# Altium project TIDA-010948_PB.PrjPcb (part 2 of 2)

## Sheet TIDA-010948_PB_Communication.SchDoc
size A2; Date: Not shown in title block; ApprovedBy: Not shown in title block; CheckedBy: Not shown in title block; Author: Not shown in title block; CompanyName: Not shown in title block; Engineer: Not shown in title block; Organization: Not shown in title block; Address1: Not shown in title block; Address2: Not shown in title block; Address3: Not shown in title block; Address4: Not shown in title block; DocumentNumber: 1; Revision: Use project parameter SCH_Rev; SheetNumber: 7; SheetTotal: 10; PageSetup: Record=PageOptions¦CenterHorizontal=True¦CenterVertical=True¦PrintScale=0.69¦XCorrection=1.00¦YCorrection=1.00¦PrintKind=0¦BorderSize=5000000¦LeftOffset=0¦BottomOffset=0¦Orientation=2¦PaperLength=1000¦PaperWidth=1000¦Scale=100¦PaperSource=15¦PrintQuality=600¦MediaType=1¦DitherType=10¦PaperKind=Letter¦PrintScaleMode=1
Used 5 times, as channels U_Communication_1, U_Communication_2, U_Communication_3, U_Communication_4, U_Communication_5. Parts and nets are listed once, with the designators drawn on the sheet.
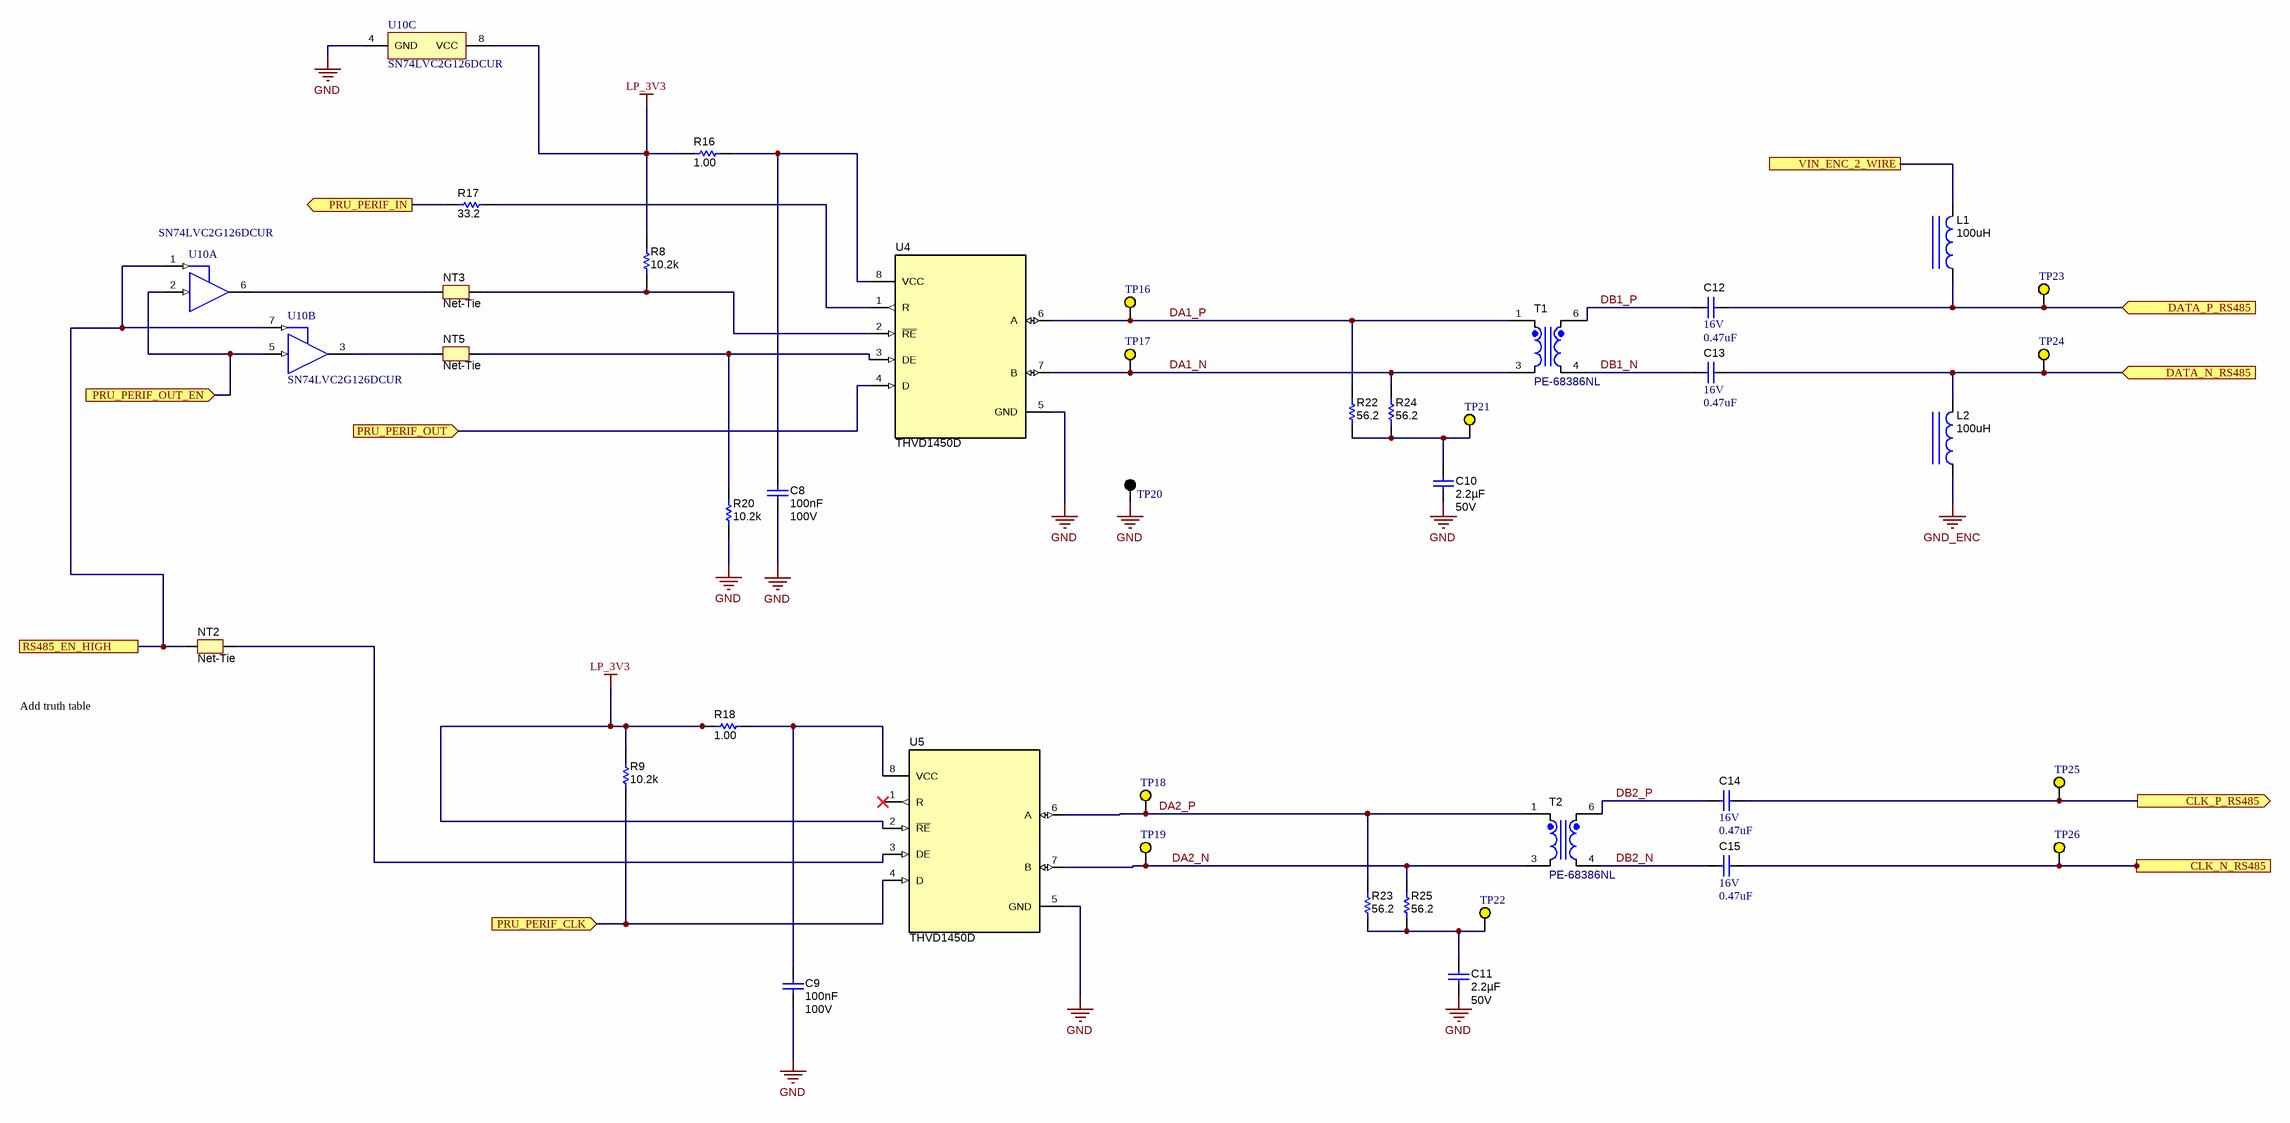
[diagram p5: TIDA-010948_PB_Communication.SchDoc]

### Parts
C8  Cap_F: 100nF  VDC_V: 100V  [0603L]  (hidden comment: GRM188R72A104KA35D)
C9  Cap_F: 100nF  VDC_V: 100V  [0603L]  (hidden comment: GRM188R72A104KA35D)
C10  Cap_F: 2.2µF  VDC_V: 50V  [0805L]  (hidden comment: CGA4J3X7R1H225K125AB)
C11  Cap_F: 2.2µF  VDC_V: 50V  [0805L]  (hidden comment: CGA4J3X7R1H225K125AB)
C12  VDC_V: 16V  ValueDisplayed: 0.47uF  [1206L]  (hidden comment: ECPU1C474MA5)
C13  VDC_V: 16V  ValueDisplayed: 0.47uF  [1206L]  (hidden comment: ECPU1C474MA5)
C14  VDC_V: 16V  ValueDisplayed: 0.47uF  [1206L]  (hidden comment: ECPU1C474MA5)
C15  VDC_V: 16V  ValueDisplayed: 0.47uF  [1206L]  (hidden comment: ECPU1C474MA5)
L1  ValueDisplayed: 100uH  [WE-TPC_4828]  (hidden comment: 744043101)
L2  ValueDisplayed: 100uH  [WE-TPC_4828]  (hidden comment: 744043101)
NT2  Net-Tie  [Net-Tie_0805_HV_NoOverlay]  (net tie, no BOM)
NT3  Net-Tie  [Net-Tie_0805_HV_NoOverlay]  (net tie, no BOM)
NT5  Net-Tie  [Net-Tie_0805_HV_NoOverlay]  (net tie, no BOM)
R8  ValueDisplayed: 10.2k  [0603L]  (hidden comment: CRCW060310K2FKEA)
R9  ValueDisplayed: 10.2k  [0603L]  (hidden comment: CRCW060310K2FKEA)
R16  ValueDisplayed: 1.00  [0603L]  (hidden comment: CRCW06031R00FKEA)
R17  ValueDisplayed: 33.2  [0603L]  (hidden comment: CRCW060333R2FKEA)
R18  ValueDisplayed: 1.00  [0603L]  (hidden comment: CRCW06031R00FKEA)
R20  ValueDisplayed: 10.2k  [0603L]  (hidden comment: CRCW060310K2FKEA)
R22  ValueDisplayed: 56.2  [0603L]  (hidden comment: CRCW060356R2FKEA)
R23  ValueDisplayed: 56.2  [0603L]  (hidden comment: CRCW060356R2FKEA)
R24  ValueDisplayed: 56.2  [0603L]  (hidden comment: CRCW060356R2FKEA)
R25  ValueDisplayed: 56.2  [0603L]  (hidden comment: CRCW060356R2FKEA)
T1  PE-68386NL  [PULSE_PE-68386NL]
T2  PE-68386NL  [PULSE_PE-68386NL]
TP16  5004  [Keystone5004]  (value not drawn)
TP17  5004  [Keystone5004]  (value not drawn)
TP18  5004  [Keystone5004]  (value not drawn)
TP19  5004  [Keystone5004]  (value not drawn)
TP20  5001  [Keystone5001]  (value not drawn)
TP21  5004  [Keystone5004]  (value not drawn)
TP22  5004  [Keystone5004]  (value not drawn)
TP23  5004  [Keystone5004]  (value not drawn)
TP24  5004  [Keystone5004]  (value not drawn)
TP25  5004  [Keystone5004]  (value not drawn)
TP26  5004  [Keystone5004]  (value not drawn)
U4  THVD1450D  [D0008A_N]
U5  THVD1450D  [D0008A_N]
U10  SN74LVC2G126DCUR  [DCU0008A_N]  (parts A,B,C of 3)

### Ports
CLK_N_RS485 (out), CLK_P_RS485 (out), DATA_N_RS485 (in), DATA_P_RS485 (in), PRU_PERIF_CLK (in), PRU_PERIF_IN (out), PRU_PERIF_OUT (in), PRU_PERIF_OUT_EN (in), RS485_EN_HIGH, VIN_ENC_2_WIRE

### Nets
GND: C8.2 C9.2 C10.2 C11.2 R20.1 TP20.1 U4.5(GND) U5.5(GND) U10.4(GND)
GND_ENC: L2.1
LP_3V3: R8.2 R9.2 R16.1 R18.1 U5.2(~{RE}) U10.8(VCC)
CLK_N_RS485: C15.1 TP26.1 ; port CLK_N_RS485
CLK_P_RS485: C14.1 TP25.1 ; port CLK_P_RS485
DA1_N: R24.2 T1.3 TP17.1 U4.7(B)
DA1_P: R22.2 T1.1 TP16.1 U4.6(A)
DA2_N: R25.2 T2.3 TP19.1 U5.7(B)
DA2_P: R23.2 T2.1 TP18.1 U5.6(A)
DATA_N_RS485: C13.1 L2.2 TP24.1 ; port DATA_N_RS485
DATA_P_RS485: C12.1 L1.1 TP23.1 ; port DATA_P_RS485
DB1_N: C13.2 T1.4
DB1_P: C12.2 T1.6
DB2_N: C15.2 T2.4
DB2_P: C14.2 T2.6
PRU_PERIF_CLK: R9.1 U5.4(D) ; port PRU_PERIF_CLK
PRU_PERIF_IN: R17.1 ; port PRU_PERIF_IN
PRU_PERIF_OUT: U4.4(D) ; port PRU_PERIF_OUT
PRU_PERIF_OUT_EN: U10.2(1A) U10.5(2A) ; port PRU_PERIF_OUT_EN
RS485_EN_HIGH: NT2.1 U10.1(1OE) U10.7(2OE) ; port RS485_EN_HIGH
VIN_ENC_2_WIRE: L1.2 ; port VIN_ENC_2_WIRE
NetC8_1: C8.1 R16.2 U4.8(VCC)
NetC9_1: C9.1 R18.2 U5.8(VCC)
NetC10_1: C10.1 R22.1 R24.1 TP21.1
NetC11_1: C11.1 R23.1 R25.1 TP22.1
NetNT2_2: NT2.2 U5.3(DE)
NetNT3_1: NT3.1 U10.6(1Y)
NetNT3_2: NT3.2 R8.1 U4.2(~{RE})
NetNT5_1: NT5.1 U10.3(2Y)
NetNT5_2: NT5.2 R20.2 U4.3(DE)
NetR17_2: R17.2 U4.1(R)

Not connected (* = marked no-connect by the designer): U5 1(R)*

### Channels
U_Communication_1: designators end in A; ports CLK_N_RS485=CLK_N CLK_P_RS485=CLK_P DATA_N_RS485=DATA_N DATA_P_RS485=DATA_P PRU_PERIF_CLK=eQEP3_A / PRU0_PERIF0_CLK PRU_PERIF_IN=PRU0_PERIF0_IN PRU_PERIF_OUT=eQEP3_B / PRU0_PERIF0_OUT PRU_PERIF_OUT_EN=eQEP4_A / PRU0_PERIF0_OUT_EN RS485_EN_HIGH=RS485_EN_HIGH VIN_ENC_2_WIRE=VOUT_ENC_2_WIRE_B
U_Communication_2: designators end in B; ports CLK_N_RS485=CLK_N CLK_P_RS485=CLK_P DATA_N_RS485=DATA_N DATA_P_RS485=DATA_P PRU_PERIF_CLK=eQEP4_B / PRU0_PERIF1_CLK PRU_PERIF_IN=PRU0_PERIF1_IN PRU_PERIF_OUT=eQEP5_A / PRU0_PERIF1_OUT PRU_PERIF_OUT_EN=eQEP5_B / PRU0_PERIF1_OUT_EN RS485_EN_HIGH=RS485_EN_HIGH VIN_ENC_2_WIRE=VOUT_ENC_2_WIRE_B
U_Communication_3: designators end in C; ports CLK_N_RS485=CLK_N CLK_P_RS485=CLK_P DATA_N_RS485=DATA_N DATA_P_RS485=DATA_P PRU_PERIF_CLK=eQEP3_I / PRU0_PERIF2_CLK PRU_PERIF_IN=PRU0_PERIF2_IN PRU_PERIF_OUT=PRU0_PERIF2_OUT PRU_PERIF_OUT_EN=eQEP5_I / PRU0_PERIF2_OUT_EN RS485_EN_HIGH=RS485_EN_HIGH VIN_ENC_2_WIRE=VOUT_ENC_2_WIRE_B
U_Communication_4: designators end in D; ports CLK_N_RS485=CLK_N CLK_P_RS485=CLK_P DATA_N_RS485=DATA_N DATA_P_RS485=DATA_P PRU_PERIF_CLK=eQEP0_A / PRU1_PERIF0_CLK PRU_PERIF_IN=eQEP0_I / PRU1_PERIF0_IN PRU_PERIF_OUT=eQEP0_B / PRU1_PERIF0_OUT PRU_PERIF_OUT_EN=PRU1_PERIF0_OUT_EN RS485_EN_HIGH=RS485_EN_HIGH VIN_ENC_2_WIRE=VOUT_ENC_2_WIRE_A
U_Communication_5: designators end in E; ports CLK_N_RS485=CLK_N CLK_P_RS485=CLK_P DATA_N_RS485=DATA_N DATA_P_RS485=DATA_P PRU_PERIF_CLK=PRU1_PERIF2_CLK PRU_PERIF_IN=PRU1_PERIF2_IN PRU_PERIF_OUT=PRU1_PERIF2_OUT PRU_PERIF_OUT_EN=PRU_PERIF_OUT_EN RS485_EN_HIGH=RS485_EN_HIGH VIN_ENC_2_WIRE=VOUT_ENC_2_WIRE_A

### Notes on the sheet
- (near NT2) Add truth table

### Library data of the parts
C8 C9 = CMP-0007469-4: CAP, CERM, 0.1 uF, 100 V, +/- 10%, X7R, 0603; Manufacturer: MuRata; TaMin_C: -55°C; Polarized: N; SizeAreaWB_mm2: 4.68; Value1: Unknown; U/M: EA; Value: 0.1uF; TaMax_C: 125°C; SizeZ_mm: 1; SizeX_mm: 1.6; SizeY_mm: 0.8; Cap_Case: 0603; SizeArea_mm2: 1.28; AEC Category: Q200
C10 C11 = CMP-0007977-2: CAP, CERM, 2.2 uF, 50 V, +/- 10%, X7R, AEC-Q200 Grade 1, 0805; Manufacturer: TDK; TaMin_C: -55°C; ESR_ohm: 3.288m; Polarized: N; SizeAreaWB_mm2: 6.75; Value1: 0.003288 ohm; U/M: EA; Value: 2.2uF; TaMax_C: 125°C; SizeZ_mm: 1.45; SizeX_mm: 2; SizeY_mm: 1.25; Cap_Case: 0805; SizeArea_mm2: 2.5; AEC Qualified: Y; IRMS_A: 3.60029A; AEC Grade: 1; AEC Category: Q200
C12-C15 = CMP-0012479-3: CAP, Film, 0.47 uF, 16 V, +/- 20%, 1206 SMD; Manufacturer: Panasonic; TaMin_C: -40°C; Polarized: N; SizeAreaWB_mm2: 10.92; Value1: Unknown; Value: 0.47uF; TaMax_C: 85°C; SizeZ_mm: 1.35; SizeX_mm: 3.2; SizeY_mm: 1.6; Cap_Case: 1206; SizeArea_mm2: 5.12; Cap_F: 470nF; AEC Category: Q200
L1 L2 = CMP-0064404-2: Inductor, Shielded Drum Core, Ferrite, 100 uH, 0.3 A, 0.52 ohm, SMD; Manufacturer: Wurth Elektronik; Isat: 0.3A @ 35% inductance drop; Irms: 0.51A @ 30C rise; Green_Lifecycle: Active; SizeAreaWB_mm2: 33.64; DCR_ohm: 0.52; Green_REACh: Passed; Value: 100uH; Imax_A: 300mA; SizeZ_mm: 3; SizeX_mm: 4.8; Value2: 0.3A; SizeArea_mm2: 23.04; Ind_H: 100µH; AEC Category: Q200
NT2 NT3 NT5 = CMP-0078142-6: Single point connection between nets.
R8 R9 R20 = CMP-0021999-4: RES, 10.2 k, 1%, 0.1 W, AEC-Q200 Grade 0, 0603; Manufacturer: Vishay-Dale; Power_W: 100mW; TempCo: 100 ppm/C; Value_Code: 10k2; Value: 10.2k; EIA_Code: E96; SizeX_mm: 1.6; SizeY_mm: 0.8; SizeZ_mm: 1; Value2: 0.1W; SizeArea_mm2: 1.28; AEC Qualified: Y; VDC_V: 75V; AEC Category: Q200; AEC Grade: 0
R16 R18 = CMP-0022170-4: RES, 1.00, 1%, 0.1 W, AEC-Q200 Grade 0, 0603; Manufacturer: Vishay-Dale; Power_W: 100mW; TempCo: 100 ppm/C; Value_Code: 1R00; Value: 1.00; EIA_Code: E96; Res_ohm: 1; SizeX_mm: 1.6; SizeY_mm: 0.8; Value2: 0.1W; SizeArea_mm2: 1.28; AEC Qualified: Y; VDC_V: 75V; AEC Category: Q200; AEC Grade: 0
R17 = CMP-0022341-4: RES, 33.2, 1%, 0.1 W, AEC-Q200 Grade 0, 0603; Manufacturer: Vishay-Dale; Power_W: 100mW; TempCo: 100 ppm/C; Value_Code: 33R2; Value: 33.2; EIA_Code: E96; SizeX_mm: 1.6; SizeY_mm: 0.8; SizeZ_mm: 1; Value2: 0.1W; SizeArea_mm2: 1.28; AEC Qualified: Y; VDC_V: 75V; AEC Category: Q200; AEC Grade: 0
R22-R25 = CMP-0022500-4: RES, 56.2, 1%, 0.1 W, AEC-Q200 Grade 0, 0603; Manufacturer: Vishay-Dale; Power_W: 100mW; TempCo: 100 ppm/C; Value_Code: 56R2; Value: 56.2; EIA_Code: E96; SizeX_mm: 1.6; SizeY_mm: 0.8; SizeZ_mm: 1; Value2: 0.1W; SizeArea_mm2: 1.28; AEC Qualified: Y; VDC_V: 75V; AEC Category: Q200; AEC Grade: 0
T1 T2 = CMP-0030422-2: Transformers, Gate Drive , 785uH, SMT; Manufacturer: Pulse Engineering; LeakageInd_H: 460nH; DCR_ohm: 0.6; Lp: 785; Ind_H: 785µH
TP16-TP19 TP21-TP26 = CMP-0055141-2: Test Point, Miniature, Yellow, TH; Manufacturer: Keystone Electronics; CNHeader: FALSE; Green_Lifecycle: Active; Green_REACh: Passed; ContactFinish: Silver; CT: TRUE
TP20 = CMP-0055138-2: Test Point, Miniature, Black, TH; Manufacturer: Keystone Electronics; CNHeader: FALSE; Green_Lifecycle: Active; Green_REACh: Passed; ContactFinish: Silver; CT: TRUE
U4 U5 = CMP-0065059-3: 3.3-V to 5-V RS-485 Transceivers With +/-18-kV IEC ESD Protection, D0008A (SOIC-8); Manufacturer: Texas Instruments; Alternate PartNumber: THVD1450DR; SizeX_mm: 4.9; SizeY_mm: 6.2; CompType: IC; SizeZ_mm: 1.75; SizeArea_mm2: 30.38; SizeAreaWB_mm2: 56.58; AEC Category: Q200; AEC Qualified: N
U10 = CMP-0051824-2: Dual Bus Buffer Gate With 3-State Outputs, DCU0008A (VSSOP-8); Manufacturer: Texas Instruments; Logic: True; Voltage(Nom)(V): 1.8,2.5,3.3,5; Input Type: CMOS/TTL; ICC @ Nom Voltage(Max)(mA): 0.01; VCC(Min)(V): 1.65; Bits(#): 2; tpd @ Nom Voltage(Max)(ns): 9.8,4.9,4,3.2; 3-State Output: Yes; Technology Family: LVC; Rating: Catalog; Output Drive (IOL/IOH)(Max)(mA): 32/-32; Schmitt Trigger: No; Output Type: CMOS; F @ Nom Voltage(Max)(Mhz): 150; VCC(Max)(V): 5.5; AEC Category: Q200; AEC Qualified: N; CompType: IC; SizeAreaWB_mm2: 12.6; SizeArea_mm2: 6.4; SizeX_mm: 3.2; SizeY_mm: 2.0; SizeZ_mm: 0.9

## Sheet TIDA-010948_PB_Connectors.SchDoc
size A2; Date: Not shown in title block; ApprovedBy: Not shown in title block; CheckedBy: Not shown in title block; Author: Not shown in title block; CompanyName: Not shown in title block; Engineer: Not shown in title block; Organization: Not shown in title block; Address1: Not shown in title block; Address2: Not shown in title block; Address3: Not shown in title block; Address4: Not shown in title block; DocumentNumber: 1; Revision: Use project parameter SCH_Rev; SheetNumber: 3; SheetTotal: 9; PageSetup: Record=PageOptions¦CenterHorizontal=True¦CenterVertical=True¦PrintScale=0.69¦XCorrection=1.00¦YCorrection=1.00¦PrintKind=0¦BorderSize=5000000¦LeftOffset=0¦BottomOffset=0¦Orientation=2¦PaperLength=1000¦PaperWidth=1000¦Scale=100¦PaperSource=15¦PrintQuality=600¦MediaType=1¦DitherType=10¦PaperKind=Letter¦PrintScaleMode=1
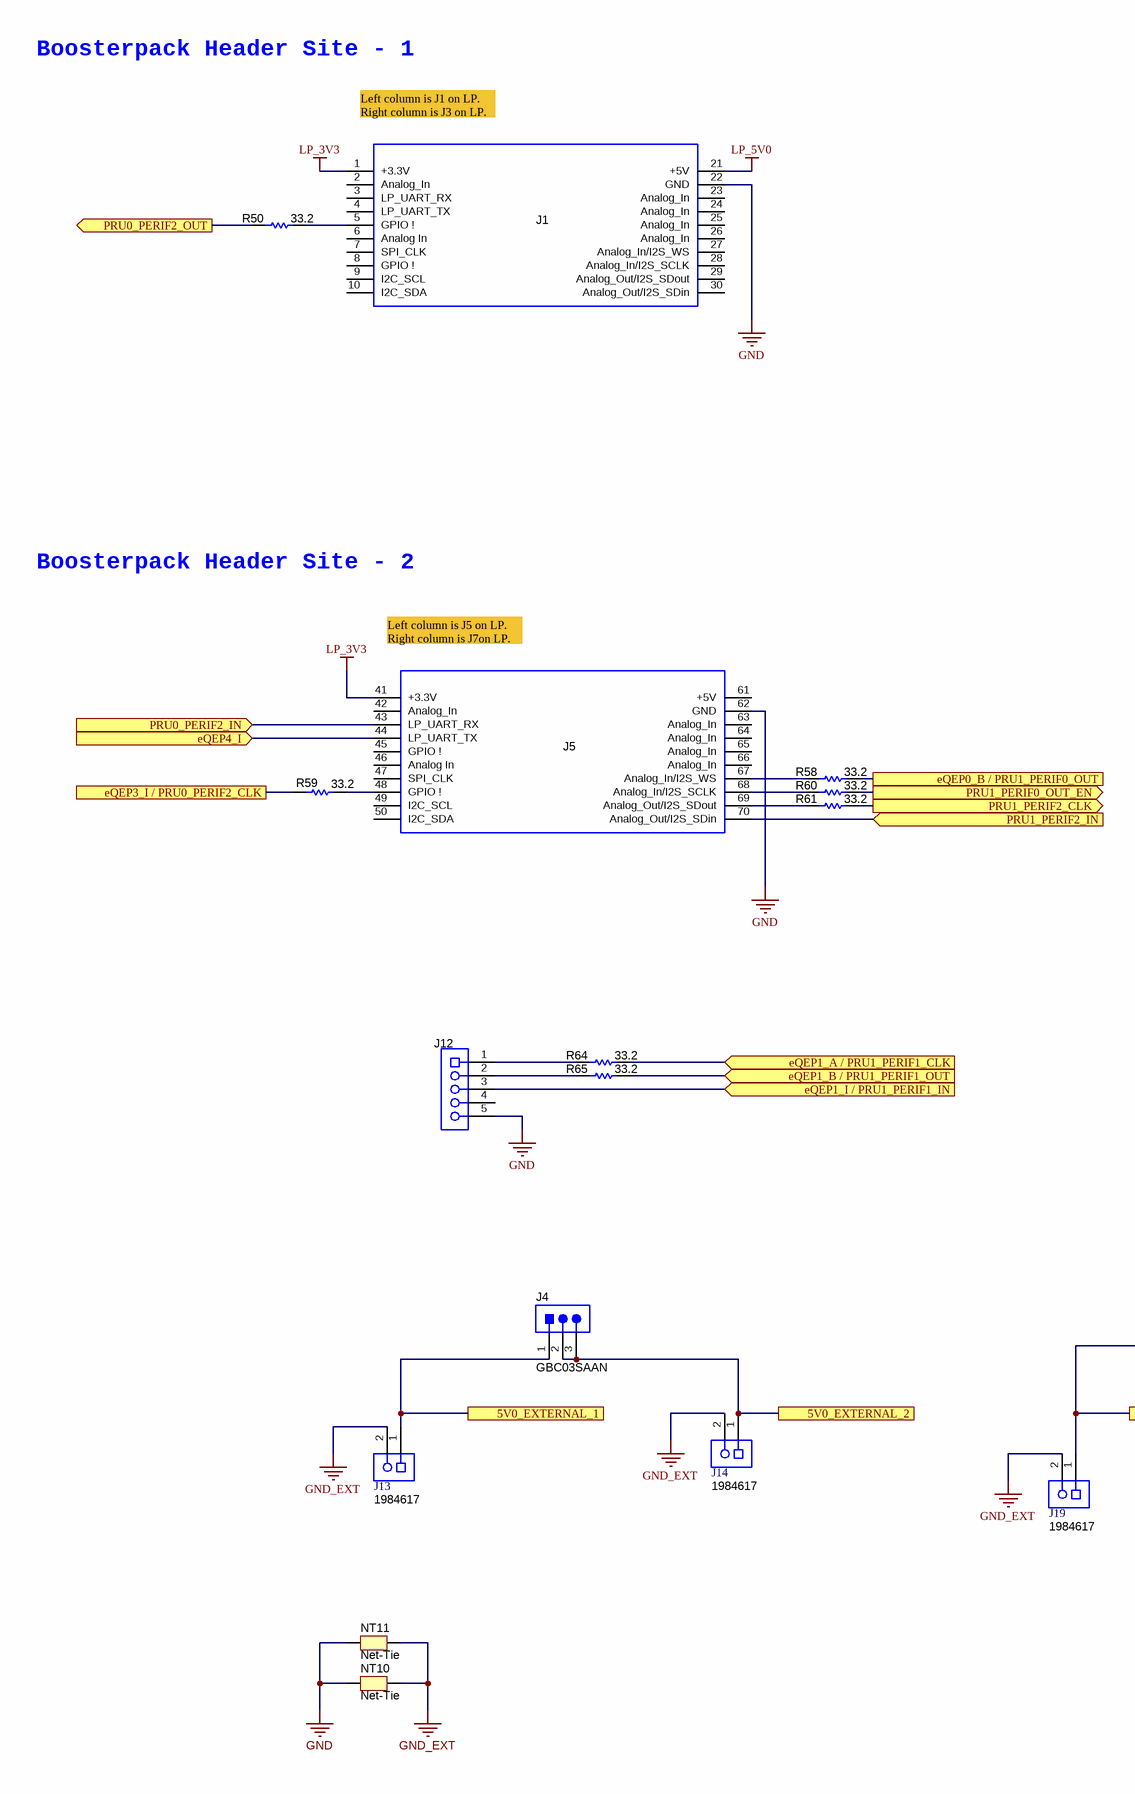
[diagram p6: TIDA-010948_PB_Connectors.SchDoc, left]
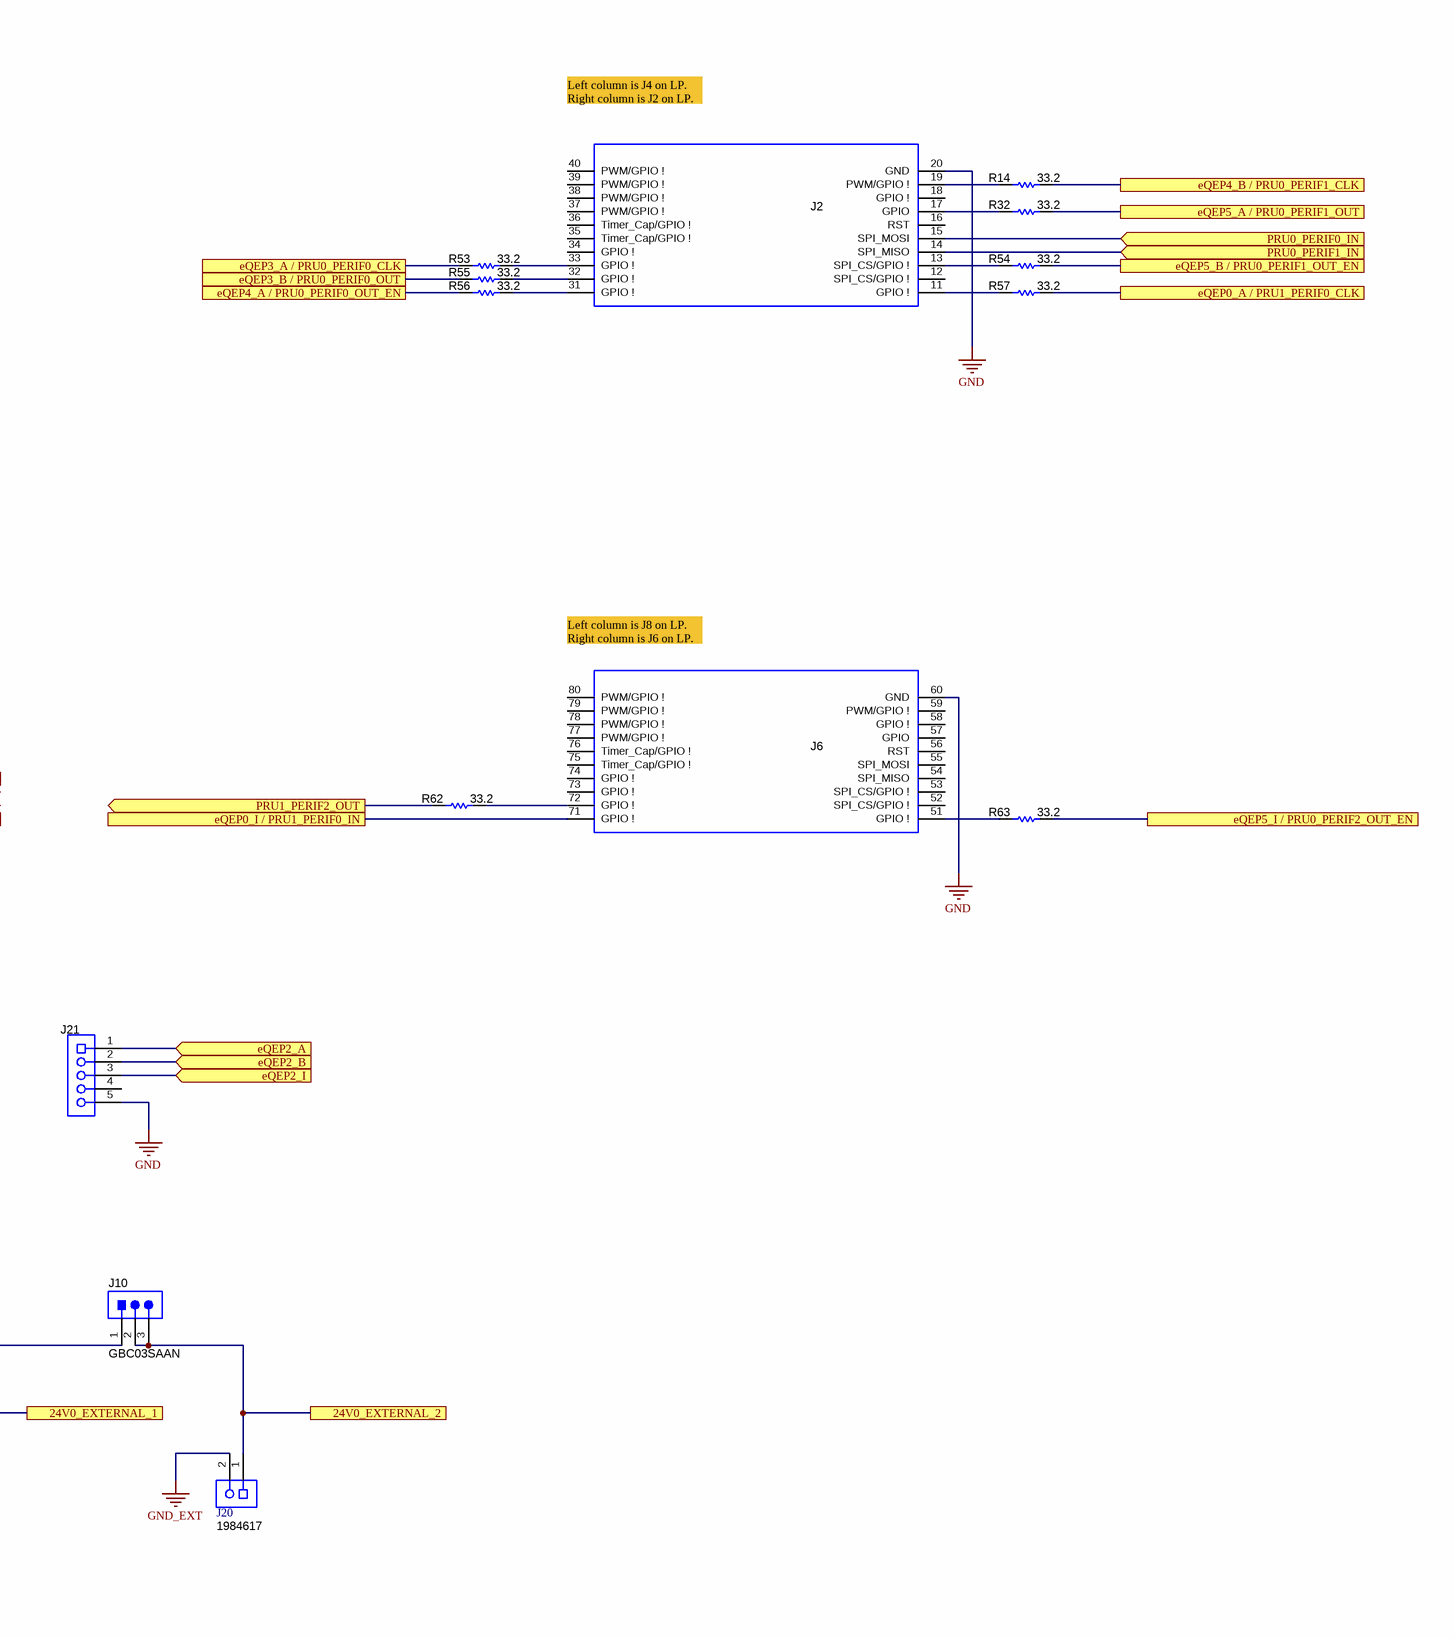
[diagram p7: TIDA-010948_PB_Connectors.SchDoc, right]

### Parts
J1  BoosterPack_40pin_J1J3  [BoosterPack_40pin_J1J3]  (value not drawn)
J2  BoosterPack_40pin_J2J4  [BoosterPack_40pin_J2J4]  (value not drawn)
J4  GBC03SAAN  [Sullins_Gxx03SAAN]
J5  BoosterPack_40pin_J5J7  [BoosterPack_40pin_J5J7]  (value not drawn)
J6  BoosterPack_40pin_J6J8  [BoosterPack_40pin_J6J8]  (value not drawn)
J10  GBC03SAAN  [Sullins_Gxx03SAAN]
J12  Receptacle_5x1  [Samtec_SSQ-105-01-x-S]  (value not drawn)
J13  1984617  [Phoenix_1984617]
J14  1984617  [Phoenix_1984617]
J19  1984617  [Phoenix_1984617]
J20  1984617  [Phoenix_1984617]
J21  Receptacle_5x1  [Samtec_SSQ-105-01-x-S]  (value not drawn)
NT10  Net-Tie  [Net-Tie_0805_HV_NoOverlay]  (net tie, no BOM)
NT11  Net-Tie  [Net-Tie_0805_HV_NoOverlay]  (net tie, no BOM)
R14  ValueDisplayed: 33.2  [0603L]  (hidden comment: CRCW060333R2FKEA)
R32  ValueDisplayed: 33.2  [0603L]  (hidden comment: CRCW060333R2FKEA)
R50  ValueDisplayed: 33.2  [0603L]  (hidden comment: CRCW060333R2FKEA)
R53  ValueDisplayed: 33.2  [0603L]  (hidden comment: CRCW060333R2FKEA)
R54  ValueDisplayed: 33.2  [0603L]  (hidden comment: CRCW060333R2FKEA)
R55  ValueDisplayed: 33.2  [0603L]  (hidden comment: CRCW060333R2FKEA)
R56  ValueDisplayed: 33.2  [0603L]  (hidden comment: CRCW060333R2FKEA)
R57  ValueDisplayed: 33.2  [0603L]  (hidden comment: CRCW060333R2FKEA)
R58  ValueDisplayed: 33.2  [0603L]  (hidden comment: CRCW060333R2FKEA)
R59  ValueDisplayed: 33.2  [0603L]  (hidden comment: CRCW060333R2FKEA)
R60  ValueDisplayed: 33.2  [0603L]  (hidden comment: CRCW060333R2FKEA)
R61  ValueDisplayed: 33.2  [0603L]  (hidden comment: CRCW060333R2FKEA)
R62  ValueDisplayed: 33.2  [0603L]  (hidden comment: CRCW060333R2FKEA)
R63  ValueDisplayed: 33.2  [0603L]  (hidden comment: CRCW060333R2FKEA)
R64  ValueDisplayed: 33.2  [0603L]  (hidden comment: CRCW060333R2FKEA)
R65  ValueDisplayed: 33.2  [0603L]  (hidden comment: CRCW060333R2FKEA)

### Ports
5V0_EXTERNAL_1, 5V0_EXTERNAL_2, 24V0_EXTERNAL_1, 24V0_EXTERNAL_2, eQEP0_A / PRU1_PERIF0_CLK, eQEP0_B / PRU1_PERIF0_OUT, eQEP0_I / PRU1_PERIF0_IN, eQEP1_A / PRU1_PERIF1_CLK (in), eQEP1_B / PRU1_PERIF1_OUT (in), eQEP1_I / PRU1_PERIF1_IN (in), eQEP2_A (in), eQEP2_B (in), eQEP2_I (in), eQEP3_A / PRU0_PERIF0_CLK, eQEP3_B / PRU0_PERIF0_OUT, eQEP3_I / PRU0_PERIF2_CLK, eQEP4_A / PRU0_PERIF0_OUT_EN, eQEP4_B / PRU0_PERIF1_CLK, eQEP4_I (in), eQEP5_A / PRU0_PERIF1_OUT, eQEP5_B / PRU0_PERIF1_OUT_EN, eQEP5_I / PRU0_PERIF2_OUT_EN, PRU0_PERIF0_IN (in), PRU0_PERIF1_IN (in), PRU0_PERIF2_IN (in), PRU0_PERIF2_OUT (out), PRU1_PERIF0_OUT_EN (out), PRU1_PERIF2_CLK (out), PRU1_PERIF2_IN (in), PRU1_PERIF2_OUT (out)

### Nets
GND: J1.22(GND) J2.20(GND) J5.62(GND) J6.60(GND) J12.5 J21.5 NT10.1 NT11.1
GND_EXT: J13.2 J14.2 J19.2 J20.2 NT10.2 NT11.2
LP_3V3: J1.1(+3.3V) J5.41(+3.3V)
LP_5V0: J1.21(+5V)
5V0_EXTERNAL_1: J4.1 J13.1 ; port 5V0_EXTERNAL_1
5V0_EXTERNAL_2: J4.2 J4.3 J14.1 ; port 5V0_EXTERNAL_2
24V0_EXTERNAL_1: J10.1 J19.1 ; port 24V0_EXTERNAL_1
24V0_EXTERNAL_2: J10.2 J10.3 J20.1 ; port 24V0_EXTERNAL_2
eQEP0_A / PRU1_PERIF0_CLK: R57.2 ; port eQEP0_A / PRU1_PERIF0_CLK
eQEP0_B / PRU1_PERIF0_OUT: R58.2 ; port eQEP0_B / PRU1_PERIF0_OUT
eQEP0_I / PRU1_PERIF0_IN: J6.71(GPIO_!) ; port eQEP0_I / PRU1_PERIF0_IN
eQEP1_A / PRU1_PERIF1_CLK: R64.2 ; port eQEP1_A / PRU1_PERIF1_CLK
eQEP1_B / PRU1_PERIF1_OUT: R65.2 ; port eQEP1_B / PRU1_PERIF1_OUT
eQEP1_I / PRU1_PERIF1_IN: J12.3 ; port eQEP1_I / PRU1_PERIF1_IN
eQEP2_A: J21.1 ; port eQEP2_A
eQEP2_B: J21.2 ; port eQEP2_B
eQEP2_I: J21.3 ; port eQEP2_I
eQEP3_A / PRU0_PERIF0_CLK: R53.1 ; port eQEP3_A / PRU0_PERIF0_CLK
eQEP3_B / PRU0_PERIF0_OUT: R55.1 ; port eQEP3_B / PRU0_PERIF0_OUT
eQEP3_I / PRU0_PERIF2_CLK: R59.1 ; port eQEP3_I / PRU0_PERIF2_CLK
eQEP4_A / PRU0_PERIF0_OUT_EN: R56.1 ; port eQEP4_A / PRU0_PERIF0_OUT_EN
eQEP4_B / PRU0_PERIF1_CLK: R14.2 ; port eQEP4_B / PRU0_PERIF1_CLK
eQEP4_I: J5.44(LP_UART_TX) ; port eQEP4_I
eQEP5_A / PRU0_PERIF1_OUT: R32.2 ; port eQEP5_A / PRU0_PERIF1_OUT
eQEP5_B / PRU0_PERIF1_OUT_EN: R54.2 ; port eQEP5_B / PRU0_PERIF1_OUT_EN
eQEP5_I / PRU0_PERIF2_OUT_EN: R63.2 ; port eQEP5_I / PRU0_PERIF2_OUT_EN
PRU0_PERIF0_IN: J2.15(SPI_MOSI) ; port PRU0_PERIF0_IN
PRU0_PERIF1_IN: J2.14(SPI_MISO) ; port PRU0_PERIF1_IN
PRU0_PERIF2_IN: J5.43(LP_UART_RX) ; port PRU0_PERIF2_IN
PRU0_PERIF2_OUT: R50.1 ; port PRU0_PERIF2_OUT
PRU1_PERIF0_OUT_EN: R60.2 ; port PRU1_PERIF0_OUT_EN
PRU1_PERIF2_CLK: R61.2 ; port PRU1_PERIF2_CLK
PRU1_PERIF2_IN: J5.70(Analog_Out/I2S_SDin) ; port PRU1_PERIF2_IN
PRU1_PERIF2_OUT: R62.1 ; port PRU1_PERIF2_OUT
NetJ1_5: J1.5(GPIO_!) R50.2
NetJ2_11: J2.11(GPIO_!) R57.1
NetJ2_13: J2.13(SPI_CS/GPIO_!) R54.1
NetJ2_17: J2.17(GPIO) R32.1
NetJ2_19: J2.19(PWM/GPIO_!) R14.1
NetJ2_31: J2.31(GPIO_!) R56.2
NetJ2_32: J2.32(GPIO_!) R55.2
NetJ2_33: J2.33(GPIO_!) R53.2
NetJ5_48: J5.48(GPIO_!) R59.2
NetJ5_67: J5.67(Analog_In/I2S_WS) R58.1
NetJ5_68: J5.68(Analog_In/I2S_SCLK) R60.1
NetJ5_69: J5.69(Analog_Out/I2S_SDout) R61.1
NetJ6_51: J6.51(GPIO_!) R63.1
NetJ6_72: J6.72(GPIO_!) R62.2
NetJ12_1: J12.1 R64.1
NetJ12_2: J12.2 R65.1

Not connected (* = marked no-connect by the designer): J1 2(Analog_In) 3(LP_UART_RX) 4(LP_UART_TX) 6(Analog_In) 7(SPI_CLK) 8(GPIO_!) 9(I2C_SCL) 10(I2C_SDA) 23(Analog_In) 24(Analog_In) 25(Analog_In) 26(Analog_In) 27(Analog_In/I2S_WS) 28(Analog_In/I2S_SCLK) 29(Analog_Out/I2S_SDout) 30(Analog_Out/I2S_SDin); J2 12(SPI_CS/GPIO_!) 16(RST) 18(GPIO_!) 34(GPIO_!) 35(Timer_Cap/GPIO_!) 36(Timer_Cap/GPIO_!) 37(PWM/GPIO_!) 38(PWM/GPIO_!) 39(PWM/GPIO_!) 40(PWM/GPIO_!); J5 42(Analog_In) 45(GPIO_!) 46(Analog_In) 47(SPI_CLK) 49(I2C_SCL) 50(I2C_SDA) 61(+5V) 63(Analog_In) 64(Analog_In) 65(Analog_In) 66(Analog_In); J6 52(SPI_CS/GPIO_!) 53(SPI_CS/GPIO_!) 54(SPI_MISO) 55(SPI_MOSI) 56(RST) 57(GPIO) 58(GPIO_!) 59(PWM/GPIO_!) 73(GPIO_!) 74(GPIO_!) 75(Timer_Cap/GPIO_!) 76(Timer_Cap/GPIO_!) 77(PWM/GPIO_!) 78(PWM/GPIO_!) 79(PWM/GPIO_!) 80(PWM/GPIO_!); J12 4; J21 4

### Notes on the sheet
- Boosterpack Header Site - 1
- Left column is J4 on LP.
  Right column is J2 on LP.
- Left column is J1 on LP.
  Right column is J3 on LP.
- Boosterpack Header Site - 2
- Left column is J5 on LP.
  Right column is J7on LP.
- Left column is J8 on LP.
  Right column is J6 on LP.

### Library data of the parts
J1 = CMP-0003837-4: Receptacle, 2.54mm, 10x2, Tin, TH; Alternate Manufacturer: Major League Electronics; Alternate PartNumber: CRD-081413-A-G; Manufacturer: Samtec; PartNumber: SSQ-110-03-T-D; Green_Lifecycle: Active; Green_REACh: Incomplete; Note: Booster Pack 40 pin J1 and J3
J2 = CMP-0078266-4: Receptacle, 2.54mm, 10x2, Tin, TH; Alternate Manufacturer: Major League Electronics; Alternate PartNumber: CRD-081413-A-G; Manufacturer: Samtec; PartNumber: SSQ-110-03-T-D; Green_Lifecycle: Active; Green_REACh: Incomplete; Note: Booster Pack 40 pin J2 and J4
J4 J10 = CMP-0054577-1: Header, 2.54 mm, 3x1, Gold, TH; Manufacturer: Sullins Connector Solutions; CT: FALSE; CNHeader: TRUE
J5 = CMP-0081070-3: Receptacle, 2.54mm, 10x2, Tin, TH; Alternate Manufacturer: Major League Electronics; Alternate PartNumber: CRD-081413-A-G; Manufacturer: Samtec; PartNumber: SSQ-110-03-T-D; Green_Lifecycle: Active; Green_REACh: Incomplete; Note: Booster Pack 40 pin J5 and J7
J6 = CMP-0081071-3: Receptacle, 2.54mm, 10x2, Tin, TH; Alternate Manufacturer: Major League Electronics; Alternate PartNumber: CRD-081413-A-G; Manufacturer: Samtec; PartNumber: SSQ-110-03-T-D; Green_Lifecycle: Active; Green_REACh: Incomplete; Note: Booster Pack 40 pin J6 and J8
J12 J21 = CMP-0077539-1: Receptacle, 2.54mm, 5x1, Gold, TH; Manufacturer: Samtec; PartNumber: SSQ-105-01-G-S; Cert_CSA: Y; CompType: Socket Strip; Current_A: 6.3A; Gender: Female; Pitch_mm: 2.54; Row_Count: 1; Voltage_V: 550V
J13 J14 J19 J20 = CMP-0055519-1: Terminal Block, 3.5mm, 2x1, TH; Manufacturer: Phoenix Contact; CNHeader: FALSE; Current_A: 17.5A; Gender: Female; Cert_CULUS: Y; Voltage_V: 200V; Row_Count: 1; Pitch_mm: 3.5; CT: TRUE
NT10 NT11 = CMP-0078142-6: Single point connection between nets.
R14 R32 R50 R53-R65 = CMP-0022341-4: as R17 on sheet TIDA-010948_PB_Communication

## Sheet TIDA-010948_PB_Encoder_connector.SchDoc
size A3; Date: Not shown in title block; ApprovedBy: Not shown in title block; CheckedBy: Not shown in title block; Author: Not shown in title block; CompanyName: Not shown in title block; Engineer: Not shown in title block; Organization: Not shown in title block; Address1: Not shown in title block; Address2: Not shown in title block; Address3: Not shown in title block; Address4: Not shown in title block; DocumentNumber: 1; Revision: Use project parameter SCH_Rev; SheetNumber: 9; SheetTotal: 10; PageSetup: Record=PageOptions¦CenterHorizontal=True¦CenterVertical=True¦PrintScale=0.69¦XCorrection=1.00¦YCorrection=1.00¦PrintKind=0¦BorderSize=5000000¦LeftOffset=0¦BottomOffset=0¦Orientation=2¦PaperLength=1000¦PaperWidth=1000¦Scale=100¦PaperSource=15¦PrintQuality=600¦MediaType=1¦DitherType=10¦PaperKind=Letter¦PrintScaleMode=1
Used 6 times, as channels U_Encoder_connector_1, U_Encoder_connector_2, U_Encoder_connector_3, U_Encoder_connector_4, U_Encoder_connector_5, U_Encoder_connector_6. Parts and nets are listed once, with the designators drawn on the sheet.
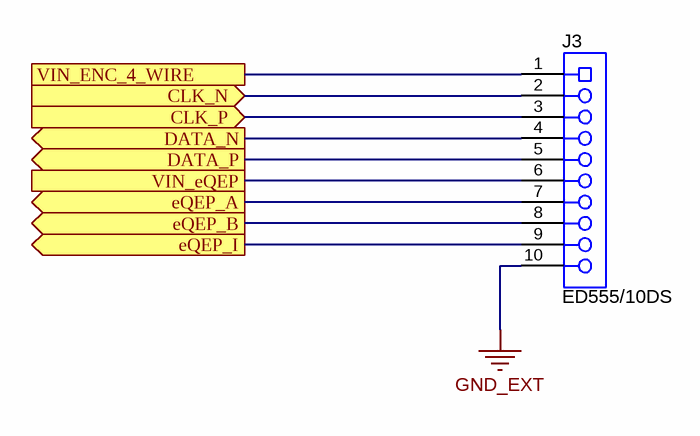
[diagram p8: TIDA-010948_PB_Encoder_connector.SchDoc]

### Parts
J3  ED555/10DS  [On-Shore_ED555_10DS]

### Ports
CLK_N (in), CLK_P (in), DATA_N (out), DATA_P (out), eQEP_A (out), eQEP_B (out), eQEP_I (out), VIN_ENC_4_WIRE, VIN_eQEP

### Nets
GND_EXT: J3.10
CLK_N: J3.2 ; port CLK_N
CLK_P: J3.3 ; port CLK_P
DATA_N: J3.4 ; port DATA_N
DATA_P: J3.5 ; port DATA_P
eQEP_A: J3.7 ; port eQEP_A
eQEP_B: J3.8 ; port eQEP_B
eQEP_I: J3.9 ; port eQEP_I
VIN_ENC_4_WIRE: J3.1 ; port VIN_ENC_4_WIRE
VIN_eQEP: J3.6 ; port VIN_eQEP

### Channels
U_Encoder_connector_1: designators end in A; ports CLK_N=CLK_N CLK_P=CLK_P DATA_N=DATA_N DATA_P=DATA_P eQEP_A=eQEP_A eQEP_B=eQEP_B eQEP_I=eQEP_I VIN_ENC_4_WIRE=VOUT__ENC_4_WIRE_A VIN_eQEP=VOUT_5V0_ENC_A
U_Encoder_connector_2: designators end in B; ports CLK_N=CLK_N CLK_P=CLK_P DATA_N=DATA_N DATA_P=DATA_P eQEP_A=eQEP1_A / PRU1_PERIF1_CLK eQEP_B=eQEP1_B / PRU1_PERIF1_OUT eQEP_I=eQEP1_I / PRU1_PERIF1_IN VIN_ENC_4_WIRE=VOUT__ENC_4_WIRE_A VIN_eQEP=VOUT_5V0_ENC_A
U_Encoder_connector_3: designators end in C; ports CLK_N=CLK_N CLK_P=CLK_P DATA_N=DATA_N DATA_P=DATA_P eQEP_A=eQEP2_A eQEP_B=eQEP2_B eQEP_I=eQEP2_I VIN_ENC_4_WIRE=VOUT__ENC_4_WIRE_A VIN_eQEP=VOUT_5V0_ENC_A
U_Encoder_connector_4: designators end in D; ports CLK_N=CLK_N CLK_P=CLK_P DATA_N=DATA_N DATA_P=DATA_P eQEP_A=eQEP_A eQEP_B=eQEP_B eQEP_I=eQEP_I VIN_ENC_4_WIRE=VOUT__ENC_4_WIRE_B VIN_eQEP=VOUT_5V0_ENC_B
U_Encoder_connector_5: designators end in E; ports CLK_N=CLK_N CLK_P=CLK_P DATA_N=DATA_N DATA_P=DATA_P eQEP_A=eQEP_A eQEP_B=eQEP_B eQEP_I=eQEP_I VIN_ENC_4_WIRE=VOUT__ENC_4_WIRE_B VIN_eQEP=VOUT_5V0_ENC_B
U_Encoder_connector_6: designators end in F; ports CLK_N=CLK_N CLK_P=CLK_P DATA_N=DATA_N DATA_P=DATA_P eQEP_A=eQEP_A eQEP_B=eQEP_B eQEP_I=eQEP_I VIN_ENC_4_WIRE=VOUT__ENC_4_WIRE_B VIN_eQEP=VOUT_5V0_ENC_B

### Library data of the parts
J3 = CMP-0084189-1: Terminal Block, 3.5mm, 10x1, TH; Manufacturer: On-Shore Technology; Pitch_mm: 3.5; Cert_VDE: Y; Gender: Female; Voltage_V: 150V; Current_A: 6A; Row_Count: 1

## Sheet TIDA-010948_PB_Level_shifter.SchDoc
size A2; Date: Not shown in title block; ApprovedBy: Not shown in title block; CheckedBy: Not shown in title block; Author: Not shown in title block; CompanyName: Not shown in title block; Engineer: Not shown in title block; Organization: Not shown in title block; Address1: Not shown in title block; Address2: Not shown in title block; Address3: Not shown in title block; Address4: Not shown in title block; DocumentNumber: 1; Revision: Use project parameter SCH_Rev; SheetNumber: 7; SheetTotal: 9; PageSetup: Record=PageOptions¦CenterHorizontal=True¦CenterVertical=True¦PrintScale=0.69¦XCorrection=1.00¦YCorrection=1.00¦PrintKind=0¦BorderSize=5000000¦LeftOffset=0¦BottomOffset=0¦Orientation=2¦PaperLength=1000¦PaperWidth=1000¦Scale=100¦PaperSource=15¦PrintQuality=600¦MediaType=1¦DitherType=10¦PaperKind=Letter¦PrintScaleMode=1
Used 2 times, as channels U_Level_shifter_1, U_Level_shifter_2. Parts and nets are listed once, with the designators drawn on the sheet.
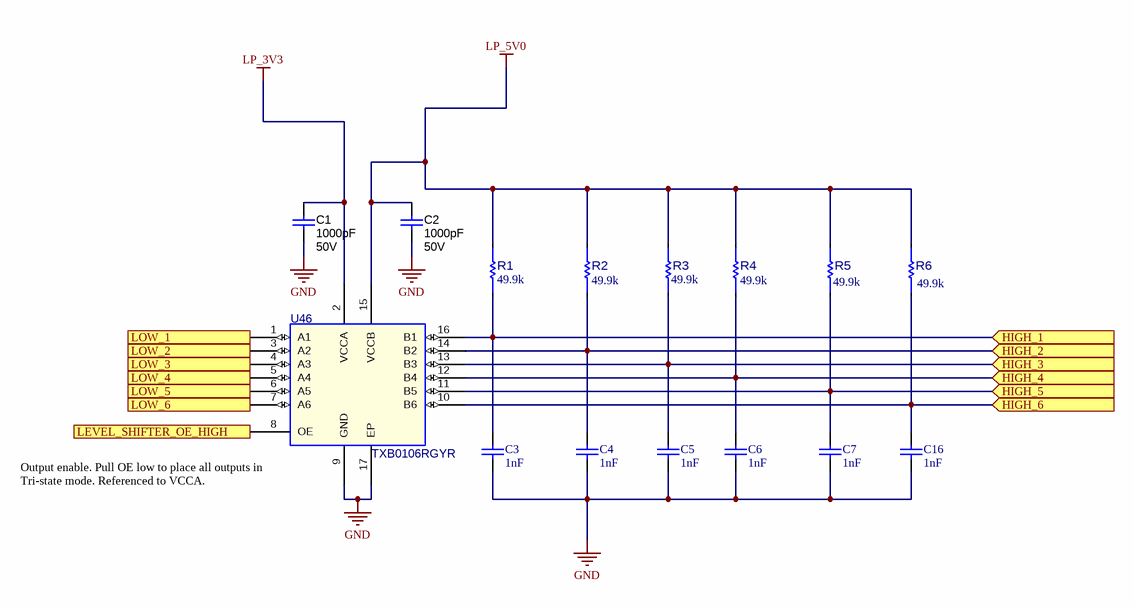
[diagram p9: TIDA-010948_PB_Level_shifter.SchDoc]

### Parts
C1  Cap_F: 1000pF  VDC_V: 50V  [0603L]  (hidden comment: GRM188R72A104KA35D)
C2  Cap_F: 1000pF  VDC_V: 50V  [0603L]  (hidden comment: GRM188R72A104KA35D)
C3  Cap_F: 1nF  [WCAP-CSGP_0603_L1.6W0.8H0.8_Reflow]  (hidden comment: 885012006085)
C4  Cap_F: 1nF  [WCAP-CSGP_0603_L1.6W0.8H0.8_Reflow]  (hidden comment: 885012006085)
C5  Cap_F: 1nF  [WCAP-CSGP_0603_L1.6W0.8H0.8_Reflow]  (hidden comment: 885012006085)
C6  Cap_F: 1nF  [WCAP-CSGP_0603_L1.6W0.8H0.8_Reflow]  (hidden comment: 885012006085)
C7  Cap_F: 1nF  [WCAP-CSGP_0603_L1.6W0.8H0.8_Reflow]  (hidden comment: 885012006085)
C16  Cap_F: 1nF  [WCAP-CSGP_0603_L1.6W0.8H0.8_Reflow]  (hidden comment: 885012006085)
R1  value 49.9k  [FP-RN73C1J49K9BTG_0603-MFG]  (hidden comment: RN73C1J49K9BTG)
R2  value 49.9k  [FP-RN73C1J49K9BTG_0603-MFG]  (hidden comment: RN73C1J49K9BTG)
R3  value 49.9k  [FP-RN73C1J49K9BTG_0603-MFG]  (hidden comment: RN73C1J49K9BTG)
R4  value 49.9k  [FP-RN73C1J49K9BTG_0603-MFG]  (hidden comment: RN73C1J49K9BTG)
R5  value 49.9k  [FP-RN73C1J49K9BTG_0603-MFG]  (hidden comment: RN73C1J49K9BTG)
R6  value 49.9k  [FP-RN73C1J49K9BTG_0603-MFG]  (hidden comment: RN73C1J49K9BTG)
U46  value TXB0106RGYR  [QFN16_19-68_160X140_1]  (hidden comment: TXB0106RGYR_VQFN16)

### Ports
HIGH_1 (in), HIGH_2 (in), HIGH_3 (in), HIGH_4 (in), HIGH_5 (in), HIGH_6 (in), LEVEL_SHIFTER_OE_HIGH, LOW_1 (out), LOW_2 (out), LOW_3 (out), LOW_4 (out), LOW_5 (out), LOW_6 (out)

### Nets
GND: C1.2 C2.2 C3.2 C4.2 C5.2 C6.2 C7.2 C16.2 U46.9(GND) U46.17(EP)
LP_3V3: C1.1 U46.2(VCCA)
LP_5V0: C2.1 R1.2 R2.2 R3.2 R4.2 R5.2 R6.2 U46.15(VCCB)
HIGH_1: C3.1 R1.1 U46.16(B1) ; port HIGH_1
HIGH_2: C4.1 R2.1 U46.14(B2) ; port HIGH_2
HIGH_3: C5.1 R3.1 U46.13(B3) ; port HIGH_3
HIGH_4: C6.1 R4.1 U46.12(B4) ; port HIGH_4
HIGH_5: C7.1 R5.1 U46.11(B5) ; port HIGH_5
HIGH_6: C16.1 R6.1 U46.10(B6) ; port HIGH_6
LEVEL_SHIFTER_OE_HIGH: U46.8(OE) ; port LEVEL_SHIFTER_OE_HIGH
LOW_1: U46.1(A1) ; port LOW_1
LOW_2: U46.3(A2) ; port LOW_2
LOW_3: U46.4(A3) ; port LOW_3
LOW_4: U46.5(A4) ; port LOW_4
LOW_5: U46.6(A5) ; port LOW_5
LOW_6: U46.7(A6) ; port LOW_6

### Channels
U_Level_shifter_1: designators end in A; ports HIGH_1=eQEP_A HIGH_2=eQEP_B HIGH_3=eQEP_I HIGH_4=eQEP_A HIGH_5=eQEP_B HIGH_6=eQEP_I LEVEL_SHIFTER_OE_HIGH=LS_OE_HIGH LOW_1=eQEP3_A / PRU0_PERIF0_CLK LOW_2=eQEP3_B / PRU0_PERIF0_OUT LOW_3=eQEP3_I / PRU0_PERIF2_CLK LOW_4=eQEP4_A / PRU0_PERIF0_OUT_EN LOW_5=eQEP4_B / PRU0_PERIF1_CLK LOW_6=eQEP4_I
U_Level_shifter_2: designators end in B; ports HIGH_1=eQEP_A HIGH_2=eQEP_B HIGH_3=eQEP_I HIGH_4=eQEP_A HIGH_5=eQEP_B HIGH_6=eQEP_I LEVEL_SHIFTER_OE_HIGH=LS_OE_HIGH LOW_1=eQEP0_A / PRU1_PERIF0_CLK LOW_2=eQEP0_B / PRU1_PERIF0_OUT LOW_3=eQEP0_I / PRU1_PERIF0_IN LOW_4=eQEP5_A / PRU0_PERIF1_OUT LOW_5=eQEP5_B / PRU0_PERIF1_OUT_EN LOW_6=eQEP5_I / PRU0_PERIF2_OUT_EN

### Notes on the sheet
- (near U46) Output enable. Pull OE low to place all outputs in Tri-state mode. Referenced to VCCA.

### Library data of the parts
C1 C2 = CMP-0007469-4: CAP, CERM, 0.1 uF, 100 V, +/- 10%, X7R, 0603; Manufacturer: MuRata; TaMin_C: -55°C; Polarized: N; SizeAreaWB_mm2: 4.68; Value1: Unknown; U/M: EA; Value: 0.1uF; TaMax_C: 125°C; SizeZ_mm: 1; SizeX_mm: 1.6; SizeY_mm: 0.8; Cap_Case: 0603; Value2: 100V; SizeArea_mm2: 1.28; AEC Category: Q200
C3-C7 C16 = CMP-0118906-1: WCAP-CSGP Multilayer Ceramic Chip Capacitor, General Purpose, size 0603, NP0, 1nF, 100VDC; Manufacturer: Wurth Elektronik; Capacitance Tolerance: +/-5%; Case/Size Code: 0603; Insulation Resistance: 10GOhm; Q Factor: 1000; Rated Voltage (DC): 100V; Technical Reference: NP00603102J100DFCT10000
R1-R6 = CMP-0093037-1: Thin Film Resistors RN 0603 49.9KΩ 0.1% 10ppm/°C; Manufacturer: TE Connectivity; Power_W: 63mW; SizeZ_mm: 0.55mm; AEC Qualified: No; VDC_V: 50V
U46 = TXB0106RGYR_VQFN16: IC 6-BIT BIDIRECTIONAL VOLTAGE-LEVEL TRANSLATOR VQFN16; Part Reference: U46; Mistral Part No: 141018020001-R; Mfr_name: TEXAS INSTRUMENTS; Part_type: ICS\INTERFACE\LEVEL TRANSLATOR; Project: NPOL_SAR_ADC; Tolerance: NA; Customs_HS_Code: 85423100; Custom_Duty: 15%

## Sheet TIDA-010948_PB_Communication_5V0.SchDoc
size A2; Date: Not shown in title block; ApprovedBy: Not shown in title block; CheckedBy: Not shown in title block; Author: Not shown in title block; CompanyName: Not shown in title block; Engineer: Not shown in title block; Organization: Not shown in title block; Address1: Not shown in title block; Address2: Not shown in title block; Address3: Not shown in title block; Address4: Not shown in title block; DocumentNumber: 1; Revision: Use project parameter SCH_Rev; SheetNumber: 10; SheetTotal: 10; PageSetup: Record=PageOptions¦CenterHorizontal=True¦CenterVertical=True¦PrintScale=0.69¦XCorrection=1.00¦YCorrection=1.00¦PrintKind=0¦BorderSize=5000000¦LeftOffset=0¦BottomOffset=0¦Orientation=2¦PaperLength=1000¦PaperWidth=1000¦Scale=100¦PaperSource=15¦PrintQuality=600¦MediaType=1¦DitherType=10¦PaperKind=Letter¦PrintScaleMode=1
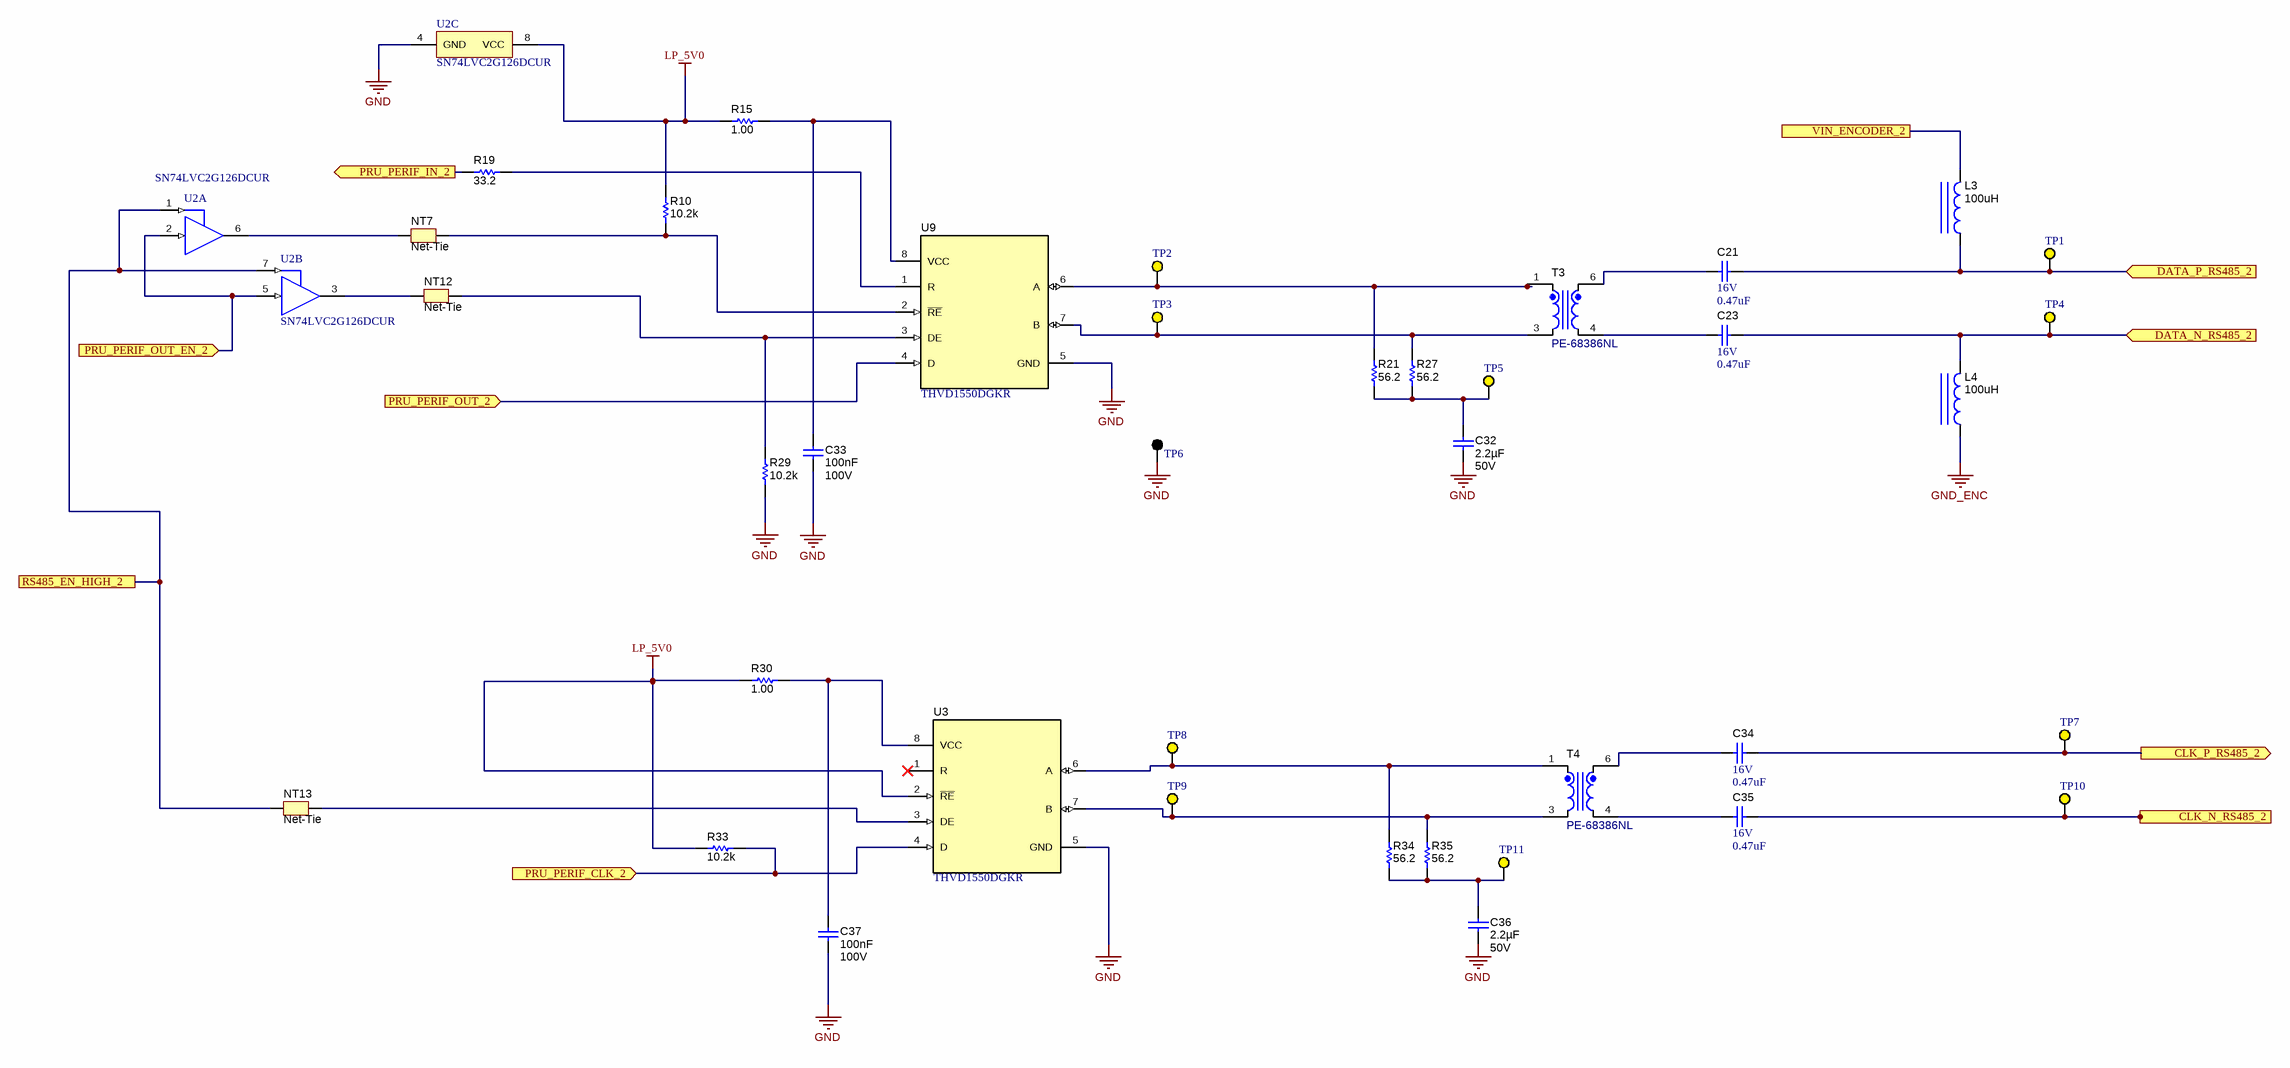
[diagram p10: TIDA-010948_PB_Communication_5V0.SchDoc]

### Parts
C21  VDC_V: 16V  ValueDisplayed: 0.47uF  [1206L]  (hidden comment: ECPU1C474MA5)
C23  VDC_V: 16V  ValueDisplayed: 0.47uF  [1206L]  (hidden comment: ECPU1C474MA5)
C32  Cap_F: 2.2µF  VDC_V: 50V  [0805L]  (hidden comment: CGA4J3X7R1H225K125AB)
C33  Cap_F: 100nF  VDC_V: 100V  [0603L]  (hidden comment: GRM188R72A104KA35D)
C34  VDC_V: 16V  ValueDisplayed: 0.47uF  [1206L]  (hidden comment: ECPU1C474MA5)
C35  VDC_V: 16V  ValueDisplayed: 0.47uF  [1206L]  (hidden comment: ECPU1C474MA5)
C36  Cap_F: 2.2µF  VDC_V: 50V  [0805L]  (hidden comment: CGA4J3X7R1H225K125AB)
C37  Cap_F: 100nF  VDC_V: 100V  [0603L]  (hidden comment: GRM188R72A104KA35D)
L3  ValueDisplayed: 100uH  [WE-TPC_4828]  (hidden comment: 744043101)
L4  ValueDisplayed: 100uH  [WE-TPC_4828]  (hidden comment: 744043101)
NT7  Net-Tie  [Net-Tie_0805_HV_NoOverlay]  (net tie, no BOM)
NT12  Net-Tie  [Net-Tie_0805_HV_NoOverlay]  (net tie, no BOM)
NT13  Net-Tie  [Net-Tie_0805_HV_NoOverlay]  (net tie, no BOM)
R10  ValueDisplayed: 10.2k  [0603L]  (hidden comment: CRCW060310K2FKEA)
R15  ValueDisplayed: 1.00  [0603L]  (hidden comment: CRCW06031R00FKEA)
R19  ValueDisplayed: 33.2  [0603L]  (hidden comment: CRCW060333R2FKEA)
R21  ValueDisplayed: 56.2  [0603L]  (hidden comment: CRCW060356R2FKEA)
R27  ValueDisplayed: 56.2  [0603L]  (hidden comment: CRCW060356R2FKEA)
R29  ValueDisplayed: 10.2k  [0603L]  (hidden comment: CRCW060310K2FKEA)
R30  ValueDisplayed: 1.00  [0603L]  (hidden comment: CRCW06031R00FKEA)
R33  ValueDisplayed: 10.2k  [0603L]  (hidden comment: CRCW060310K2FKEA)
R34  ValueDisplayed: 56.2  [0603L]  (hidden comment: CRCW060356R2FKEA)
R35  ValueDisplayed: 56.2  [0603L]  (hidden comment: CRCW060356R2FKEA)
T3  PE-68386NL  [PULSE_PE-68386NL]
T4  PE-68386NL  [PULSE_PE-68386NL]
TP1  5004  [Keystone5004]  (value not drawn)
TP2  5004  [Keystone5004]  (value not drawn)
TP3  5004  [Keystone5004]  (value not drawn)
TP4  5004  [Keystone5004]  (value not drawn)
TP5  5004  [Keystone5004]  (value not drawn)
TP6  5001  [Keystone5001]  (value not drawn)
TP7  5004  [Keystone5004]  (value not drawn)
TP8  5004  [Keystone5004]  (value not drawn)
TP9  5004  [Keystone5004]  (value not drawn)
TP10  5004  [Keystone5004]  (value not drawn)
TP11  5004  [Keystone5004]  (value not drawn)
U2  SN74LVC2G126DCUR  [DCU0008A_N]  (parts A,B,C of 3)
U3  THVD1550DGKR  [DGK0008A_N]
U9  THVD1550DGKR  [DGK0008A_N]

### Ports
CLK_N_RS485_2 (out), CLK_P_RS485_2 (out), DATA_N_RS485_2 (in), DATA_P_RS485_2 (in), PRU_PERIF_CLK_2 (in), PRU_PERIF_IN_2 (out), PRU_PERIF_OUT_2 (in), PRU_PERIF_OUT_EN_2 (in), RS485_EN_HIGH_2, VIN_ENCODER_2

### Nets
GND: C32.2 C33.2 C36.2 C37.2 R29.1 TP6.1 U2.4(GND) U3.5(GND) U9.5(GND)
GND_ENC: L4.1
LP_5V0: R10.2 R15.1 R30.1 R33.2 U2.8(VCC) U3.2(~{RE})
CLK_N: C35.1 TP10.1 ; port CLK_N_RS485_2
CLK_P: C34.1 TP7.1 ; port CLK_P_RS485_2
DATA_N: C23.1 L4.2 TP4.1 ; port DATA_N_RS485_2
DATA_P: C21.1 L3.1 TP1.1 ; port DATA_P_RS485_2
eQEP1_A / PRU1_PERIF1_CLK: R33.1 U3.4(D) ; port PRU_PERIF_CLK_2
eQEP1_B / PRU1_PERIF1_OUT: U9.4(D) ; port PRU_PERIF_OUT_2
eQEP1_I / PRU1_PERIF1_IN: R19.1 ; port PRU_PERIF_IN_2
PRU_PERIF_OUT_EN_2: U2.2(1A) U2.5(2A) ; port PRU_PERIF_OUT_EN_2
RS485_EN_HIGH: NT13.1 U2.1(1OE) U2.7(2OE) ; port RS485_EN_HIGH_2
VOUT_ENC_2_WIRE_A: L3.2 ; port VIN_ENCODER_2
NetC21_2: C21.2 T3.6
NetC23_2: C23.2 T3.4
NetC32_1: C32.1 R21.1 R27.1 TP5.1
NetC33_1: C33.1 R15.2 U9.8(VCC)
NetC34_2: C34.2 T4.6
NetC35_2: C35.2 T4.4
NetC36_1: C36.1 R34.1 R35.1 TP11.1
NetC37_1: C37.1 R30.2 U3.8(VCC)
NetNT7_1: NT7.1 U2.6(1Y)
NetNT7_2: NT7.2 R10.1 U9.2(~{RE})
NetNT12_1: NT12.1 U2.3(2Y)
NetNT12_2: NT12.2 R29.2 U9.3(DE)
NetNT13_2: NT13.2 U3.3(DE)
NetR19_2: R19.2 U9.1(R)
NetR21_2: R21.2 T3.1 TP2.1 U9.6(A)
NetR27_2: R27.2 T3.3 TP3.1 U9.7(B)
NetR34_2: R34.2 T4.1 TP8.1 U3.6(A)
NetR35_2: R35.2 T4.3 TP9.1 U3.7(B)

Not connected (* = marked no-connect by the designer): U3 1(R)*

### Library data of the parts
C21 C23 C34 C35 = CMP-0012479-3: as C12 on sheet TIDA-010948_PB_Communication
C32 C36 = CMP-0007977-2: as C10 on sheet TIDA-010948_PB_Communication
C33 C37 = CMP-0007469-4: as C8 on sheet TIDA-010948_PB_Communication
L3 L4 = CMP-0064404-2: as L1 on sheet TIDA-010948_PB_Communication
NT7 NT12 NT13 = CMP-0078142-6: Single point connection between nets.
R10 R29 R33 = CMP-0021999-4: as R8 on sheet TIDA-010948_PB_Communication
R15 R30 = CMP-0022170-4: as R16 on sheet TIDA-010948_PB_Communication
R19 = CMP-0022341-4: as R17 on sheet TIDA-010948_PB_Communication
R21 R27 R34 R35 = CMP-0022500-4: as R22 on sheet TIDA-010948_PB_Communication
T3 T4 = CMP-0030422-2: as T1 on sheet TIDA-010948_PB_Communication
TP1-TP5 TP7-TP11 = CMP-0055141-2: as TP16 on sheet TIDA-010948_PB_Communication
TP6 = CMP-0055138-2: as TP20 on sheet TIDA-010948_PB_Communication
U2 = CMP-0051824-2: as U10 on sheet TIDA-010948_PB_Communication
U3 U9 = CMP-0074780-3: 5-V RS-485 Transceivers With +/-18-kV IEC ESD Protection, DGK0008A (VSSOP-8); Alternate Manufacturer: Texas Instruments; SizeAreaWB_mm2: 23.6; SizeZ_mm: 1.1; SizeX_mm: 4.9; SizeY_mm: 3; SizeArea_mm2: 14.7; CompType: IC; AEC Category: Q200; AEC Qualified: N

## Sheet TIDA-010948_PB_Hardware.SchDoc
size 431 x 279 mm; Date: Not shown in title block; ApprovedBy: Not shown in title block; CheckedBy: Not shown in title block; Author: Not shown in title block; CompanyName: Not shown in title block; Engineer: Not shown in title block; Organization: Not shown in title block; Address1: Not shown in title block; Address2: Not shown in title block; Address3: Not shown in title block; Address4: Not shown in title block; DocumentNumber: 3; Revision: Use project parameter SCH_Rev; SheetNumber: 2; SheetTotal: 9; PageSetup: Record=PageOptions¦CenterHorizontal=True¦CenterVertical=True¦PrintScale=1.00¦XCorrection=1.00¦YCorrection=1.00¦PrintKind=0¦BorderSize=5000000¦LeftOffset=0¦BottomOffset=0¦Orientation=2¦PaperLength=1000¦PaperWidth=1000¦Scale=100¦PaperSource=15¦PrintQuality=600¦MediaType=1¦DitherType=10¦PaperKind=Letter¦PrintScaleMode=1
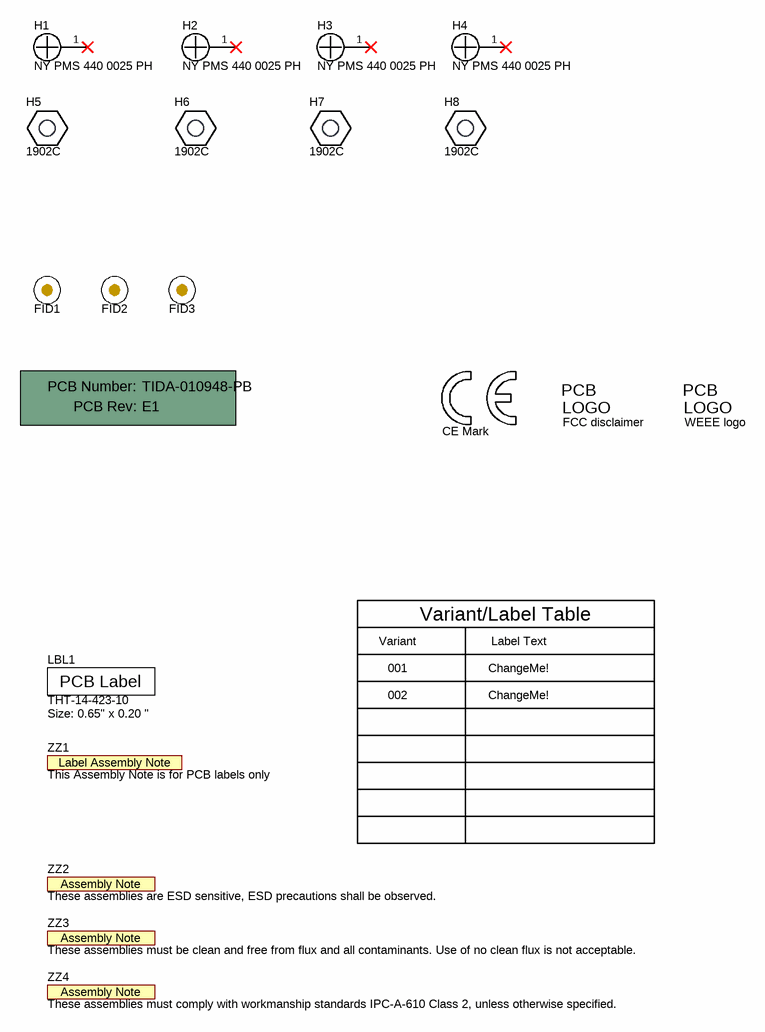
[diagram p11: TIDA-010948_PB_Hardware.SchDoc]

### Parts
!PCB  Printed Circuit Board  (value not drawn)  (mechanical)
FID1  Fiducial  [Fiducial10-20]  (value not drawn)
FID2  Fiducial  [Fiducial10-20]  (value not drawn)
FID3  Fiducial  [Fiducial10-20]  (value not drawn)
H1  NY PMS 440 0025 PH  [NY PMS 440 0025 PH]
H2  NY PMS 440 0025 PH  [NY PMS 440 0025 PH]
H3  NY PMS 440 0025 PH  [NY PMS 440 0025 PH]
H4  NY PMS 440 0025 PH  [NY PMS 440 0025 PH]
H5  1902C  [Keystone_1902C]
H6  1902C  [Keystone_1902C]
H7  1902C  [Keystone_1902C]
H8  1902C  [Keystone_1902C]
LBL1  THT-14-423-10  Note: Size: 0.65" x 0.20 "  [Label_650x200]
Logo2  CE Mark  [CE_Mark_5mm]  (no BOM)
Logo3  FCC disclaimer  [FCC_disclaimer]  (no BOM)
Logo4  WEEE logo  [WEEE_Minimum]  (no BOM)
ZZ1  This Assembly Note is for PCB labels only  [AssemblyNoteLabel]  (no BOM)
ZZ2  These assemblies are ESD sensitive, ESD precautions shall be observed.  [AssemblyNote]  (no BOM)
ZZ3  These assemblies must be clean and free from flux and all contaminants. Use of no clean flux is not acceptable.  [AssemblyNote]  (no BOM)
ZZ4  These assemblies must comply with workmanship standards IPC-A-610 Class 2, unless otherwise specified.  [AssemblyNote]  (no BOM)

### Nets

Not connected (* = marked no-connect by the designer): H1 1*; H2 1*; H3 1*; H4 1*

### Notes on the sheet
- Variant
- Variant/Label Table
- Label Text
- 001
- 002
- ChangeMe!

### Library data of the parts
!PCB = CMP-0003618-2: Manufacturer: Any; PartNumber: TIDA-010948-PB
FID1-FID3 = CMP-0077181-1: Fiducial mark.  There is nothing to buy or mount.
H1-H4 = CMP-0003617-1: Machine Screw, Round, #4-40 x 1/4, Nylon, Philips panhead; Manufacturer: B&F Fastener Supply; CompType: Hardware
H5-H8 = CMP-0003610-1: Standoff, Hex, 0.5"L #4-40 Nylon; Manufacturer: Keystone; CompType: Hardware
LBL1 = CMP-0003625-1: Thermal Transfer Printable Labels, 0.650" W x 0.200" H - 10,000 per roll; Manufacturer: Brady; CompType: Label
Logo2 = CMP-0074844-1: SymbolCreator: a0412235
Logo3 = CMP-0074847-1: FCC_disclaimer; Library Reference: Logo
Logo4 = CMP-0074769-3: Manufacturer: Texas Instruments; AEC Category: Q200; CompType: IC
ZZ1 = CMP-0003616-3
ZZ2 = CMP-0077236-1
ZZ3 = CMP-0077237-1
ZZ4 = CMP-0077238-1

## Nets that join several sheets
GND: TIDA-010948_PB (J15.1 J17.1), U_Power_1 (22 pins), U_Power_1/U_Buck_converters (14 pins), U_Communication_1 (9 pins), U_Power_2 (22 pins), U_Power_2/U_Buck_converters (14 pins), U_Communication_2 (9 pins), U_Communication_3 (9 pins), U_Communication_4 (9 pins), U_Communication_5 (9 pins), TIDA-010948_PB_Connectors (8 pins), U_Level_shifter_1 (10 pins), U_Level_shifter_2 (10 pins), TIDA-010948_PB_Communication_5V0 (9 pins)
GND_ENC: U_Power_1 (7 pins), U_Communication_1 (L2A.1), U_Power_2 (7 pins), U_Communication_2 (L2B.1), U_Communication_3 (L2C.1), U_Communication_4 (L2D.1), U_Communication_5 (L2E.1), TIDA-010948_PB_Communication_5V0 (L4.1)
GND_EXT: TIDA-010948_PB_Connectors (6 pins), U_Encoder_connector_1 (J3A.10), U_Encoder_connector_2 (J3B.10), U_Encoder_connector_3 (J3C.10), U_Encoder_connector_4 (J3D.10), U_Encoder_connector_5 (J3E.10), U_Encoder_connector_6 (J3F.10)
LP_3V3: TIDA-010948_PB (J15.3 J17.3 J18.4), U_Communication_1 (6 pins), U_Communication_2 (6 pins), U_Communication_3 (6 pins), U_Communication_4 (6 pins), U_Communication_5 (6 pins), TIDA-010948_PB_Connectors (J1.1 J5.41), U_Level_shifter_1 (C1A.1 U46A.2), U_Level_shifter_2 (C1B.1 U46B.2)
LP_5V0: TIDA-010948_PB_Connectors (J1.21), U_Level_shifter_1 (8 pins), U_Level_shifter_2 (8 pins), TIDA-010948_PB_Communication_5V0 (6 pins)
5V0_EXTERNAL_1: U_Power_1 (NT4A.1), TIDA-010948_PB_Connectors (J4.1 J13.1)
5V0_EXTERNAL_2: U_Power_2 (NT4B.1), TIDA-010948_PB_Connectors (J4.2 J4.3 J14.1)
11V0_12V0: U_Power_1 (NT1A.1), U_Power_1/U_Buck_converters (5 pins)
11V0_12V0: U_Power_2 (NT1B.1), U_Power_2/U_Buck_converters (5 pins)
24V0_EXTERNAL_1: U_Power_1/U_Buck_converters (D6A.2), TIDA-010948_PB_Connectors (J10.1 J19.1)
24V0_EXTERNAL_2: U_Power_2/U_Buck_converters (D6B.2), TIDA-010948_PB_Connectors (J10.2 J10.3 J20.1)
CLK_N: U_Communication_1 (C15A.1 TP26A.1), U_Encoder_connector_4 (J3D.2)
CLK_N: U_Communication_2 (C15B.1 TP26B.1), U_Encoder_connector_5 (J3E.2)
CLK_N: U_Communication_3 (C15C.1 TP26C.1), U_Encoder_connector_6 (J3F.2)
CLK_N: U_Communication_4 (C15D.1 TP26D.1), U_Encoder_connector_1 (J3A.2)
CLK_N: U_Communication_5 (C15E.1 TP26E.1), U_Encoder_connector_3 (J3C.2)
CLK_N: U_Encoder_connector_2 (J3B.2), TIDA-010948_PB_Communication_5V0 (C35.1 TP10.1)
CLK_P: U_Communication_1 (C14A.1 TP25A.1), U_Encoder_connector_4 (J3D.3)
CLK_P: U_Communication_2 (C14B.1 TP25B.1), U_Encoder_connector_5 (J3E.3)
CLK_P: U_Communication_3 (C14C.1 TP25C.1), U_Encoder_connector_6 (J3F.3)
CLK_P: U_Communication_4 (C14D.1 TP25D.1), U_Encoder_connector_1 (J3A.3)
CLK_P: U_Communication_5 (C14E.1 TP25E.1), U_Encoder_connector_3 (J3C.3)
CLK_P: U_Encoder_connector_2 (J3B.3), TIDA-010948_PB_Communication_5V0 (C34.1 TP7.1)
DATA_N: U_Communication_1 (C13A.1 L2A.2 TP24A.1), U_Encoder_connector_4 (J3D.4)
DATA_N: U_Communication_2 (C13B.1 L2B.2 TP24B.1), U_Encoder_connector_5 (J3E.4)
DATA_N: U_Communication_3 (C13C.1 L2C.2 TP24C.1), U_Encoder_connector_6 (J3F.4)
DATA_N: U_Communication_4 (C13D.1 L2D.2 TP24D.1), U_Encoder_connector_1 (J3A.4)
DATA_N: U_Communication_5 (C13E.1 L2E.2 TP24E.1), U_Encoder_connector_3 (J3C.4)
DATA_N: U_Encoder_connector_2 (J3B.4), TIDA-010948_PB_Communication_5V0 (C23.1 L4.2 TP4.1)
DATA_P: U_Communication_1 (C12A.1 L1A.1 TP23A.1), U_Encoder_connector_4 (J3D.5)
DATA_P: U_Communication_2 (C12B.1 L1B.1 TP23B.1), U_Encoder_connector_5 (J3E.5)
DATA_P: U_Communication_3 (C12C.1 L1C.1 TP23C.1), U_Encoder_connector_6 (J3F.5)
DATA_P: U_Communication_4 (C12D.1 L1D.1 TP23D.1), U_Encoder_connector_1 (J3A.5)
DATA_P: U_Communication_5 (C12E.1 L1E.1 TP23E.1), U_Encoder_connector_3 (J3C.5)
DATA_P: U_Encoder_connector_2 (J3B.5), TIDA-010948_PB_Communication_5V0 (C21.1 L3.1 TP1.1)
eQEP0_A / PRU1_PERIF0_CLK: U_Communication_4 (R9D.1 U5D.4), TIDA-010948_PB_Connectors (R57.2), U_Level_shifter_2 (U46B.1)
eQEP0_B / PRU1_PERIF0_OUT: U_Communication_4 (U4D.4), TIDA-010948_PB_Connectors (R58.2), U_Level_shifter_2 (U46B.3)
eQEP0_I / PRU1_PERIF0_IN: U_Communication_4 (R17D.1), TIDA-010948_PB_Connectors (J6.71), U_Level_shifter_2 (U46B.4)
eQEP1_A / PRU1_PERIF1_CLK: TIDA-010948_PB_Connectors (R64.2), U_Encoder_connector_2 (J3B.7), TIDA-010948_PB_Communication_5V0 (R33.1 U3.4)
eQEP1_B / PRU1_PERIF1_OUT: TIDA-010948_PB_Connectors (R65.2), U_Encoder_connector_2 (J3B.8), TIDA-010948_PB_Communication_5V0 (U9.4)
eQEP1_I / PRU1_PERIF1_IN: TIDA-010948_PB_Connectors (J12.3), U_Encoder_connector_2 (J3B.9), TIDA-010948_PB_Communication_5V0 (R19.1)
eQEP2_A: TIDA-010948_PB_Connectors (J21.1), U_Encoder_connector_3 (J3C.7)
eQEP2_B: TIDA-010948_PB_Connectors (J21.2), U_Encoder_connector_3 (J3C.8)
eQEP2_I: TIDA-010948_PB_Connectors (J21.3), U_Encoder_connector_3 (J3C.9)
eQEP3_A / PRU0_PERIF0_CLK: U_Communication_1 (R9A.1 U5A.4), TIDA-010948_PB_Connectors (R53.1), U_Level_shifter_1 (U46A.1)
eQEP3_B / PRU0_PERIF0_OUT: U_Communication_1 (U4A.4), TIDA-010948_PB_Connectors (R55.1), U_Level_shifter_1 (U46A.3)
eQEP3_I / PRU0_PERIF2_CLK: U_Communication_3 (R9C.1 U5C.4), TIDA-010948_PB_Connectors (R59.1), U_Level_shifter_1 (U46A.4)
eQEP4_A / PRU0_PERIF0_OUT_EN: U_Communication_1 (U10A.2 U10A.5), TIDA-010948_PB_Connectors (R56.1), U_Level_shifter_1 (U46A.5)
eQEP4_B / PRU0_PERIF1_CLK: U_Communication_2 (R9B.1 U5B.4), TIDA-010948_PB_Connectors (R14.2), U_Level_shifter_1 (U46A.6)
eQEP4_I: TIDA-010948_PB_Connectors (J5.44), U_Level_shifter_1 (U46A.7)
eQEP5_A / PRU0_PERIF1_OUT: U_Communication_2 (U4B.4), TIDA-010948_PB_Connectors (R32.2), U_Level_shifter_2 (U46B.5)
eQEP5_B / PRU0_PERIF1_OUT_EN: U_Communication_2 (U10B.2 U10B.5), TIDA-010948_PB_Connectors (R54.2), U_Level_shifter_2 (U46B.6)
eQEP5_I / PRU0_PERIF2_OUT_EN: U_Communication_3 (U10C.2 U10C.5), TIDA-010948_PB_Connectors (R63.2), U_Level_shifter_2 (U46B.7)
eQEP_A: U_Encoder_connector_1 (J3A.7), U_Level_shifter_2 (C3B.1 R1B.1 U46B.16)
eQEP_A: U_Encoder_connector_4 (J3D.7), U_Level_shifter_1 (C3A.1 R1A.1 U46A.16)
eQEP_A: U_Encoder_connector_5 (J3E.7), U_Level_shifter_1 (C6A.1 R4A.1 U46A.12)
eQEP_A: U_Encoder_connector_6 (J3F.7), U_Level_shifter_2 (C6B.1 R4B.1 U46B.12)
eQEP_B: U_Encoder_connector_1 (J3A.8), U_Level_shifter_2 (C4B.1 R2B.1 U46B.14)
eQEP_B: U_Encoder_connector_4 (J3D.8), U_Level_shifter_1 (C4A.1 R2A.1 U46A.14)
eQEP_B: U_Encoder_connector_5 (J3E.8), U_Level_shifter_1 (C7A.1 R5A.1 U46A.11)
eQEP_B: U_Encoder_connector_6 (J3F.8), U_Level_shifter_2 (C7B.1 R5B.1 U46B.11)
eQEP_I: U_Encoder_connector_1 (J3A.9), U_Level_shifter_2 (C5B.1 R3B.1 U46B.13)
eQEP_I: U_Encoder_connector_4 (J3D.9), U_Level_shifter_1 (C5A.1 R3A.1 U46A.13)
eQEP_I: U_Encoder_connector_5 (J3E.9), U_Level_shifter_1 (C16A.1 R6A.1 U46A.10)
eQEP_I: U_Encoder_connector_6 (J3F.9), U_Level_shifter_2 (C16B.1 R6B.1 U46B.10)
LS_OE_HIGH: TIDA-010948_PB (R11.1), U_Level_shifter_1 (U46A.8), U_Level_shifter_2 (U46B.8)
PRU0_PERIF0_IN: U_Communication_1 (R17A.1), TIDA-010948_PB_Connectors (J2.15)
PRU0_PERIF1_IN: U_Communication_2 (R17B.1), TIDA-010948_PB_Connectors (J2.14)
PRU0_PERIF2_IN: U_Communication_3 (R17C.1), TIDA-010948_PB_Connectors (J5.43)
PRU0_PERIF2_OUT: U_Communication_3 (U4C.4), TIDA-010948_PB_Connectors (R50.1)
PRU1_PERIF0_OUT_EN: U_Communication_4 (U10D.2 U10D.5), TIDA-010948_PB_Connectors (R60.2)
PRU1_PERIF2_CLK: U_Communication_5 (R9E.1 U5E.4), TIDA-010948_PB_Connectors (R61.2)
PRU1_PERIF2_IN: U_Communication_5 (R17E.1), TIDA-010948_PB_Connectors (J5.70)
PRU1_PERIF2_OUT: U_Communication_5 (U4E.4), TIDA-010948_PB_Connectors (R62.1)
PRU_PERIF_OUT_EN: TIDA-010948_PB (J18.1 J18.2 J18.3), U_Communication_5 (U10E.2 U10E.5)
PRU_PERIF_OUT_EN_2: TIDA-010948_PB (J16.1 J16.2), TIDA-010948_PB_Communication_5V0 (U2.2 U2.5)
RS485_EN_HIGH: TIDA-010948_PB (R12.1), U_Communication_1 (NT2A.1 U10A.1 U10A.7), U_Communication_2 (NT2B.1 U10B.1 U10B.7), U_Communication_3 (NT2C.1 U10C.1 U10C.7), U_Communication_4 (NT2D.1 U10D.1 U10D.7), U_Communication_5 (NT2E.1 U10E.1 U10E.7), TIDA-010948_PB_Communication_5V0 (NT13.1 U2.1 U2.7)
VOUT_5V0_ENC_A: U_Power_1/U_Buck_converters (5 pins), U_Encoder_connector_1 (J3A.6), U_Encoder_connector_2 (J3B.6), U_Encoder_connector_3 (J3C.6)
VOUT_5V0_ENC_B: U_Power_2/U_Buck_converters (5 pins), U_Encoder_connector_4 (J3D.6), U_Encoder_connector_5 (J3E.6), U_Encoder_connector_6 (J3F.6)
VOUT__ENC_4_WIRE_A: TIDA-010948_PB (J7.1), U_Power_1 (7 pins), U_Encoder_connector_1 (J3A.1), U_Encoder_connector_2 (J3B.1), U_Encoder_connector_3 (J3C.1)
VOUT__ENC_4_WIRE_B: TIDA-010948_PB (J8.1), U_Power_2 (7 pins), U_Encoder_connector_4 (J3D.1), U_Encoder_connector_5 (J3E.1), U_Encoder_connector_6 (J3F.1)
VOUT_ENC_2_WIRE_A: TIDA-010948_PB (J7.2), U_Communication_4 (L1D.2), U_Communication_5 (L1E.2), TIDA-010948_PB_Communication_5V0 (L3.2)
VOUT_ENC_2_WIRE_B: TIDA-010948_PB (J8.2), U_Communication_1 (L1A.2), U_Communication_2 (L1B.2), U_Communication_3 (L1C.2)

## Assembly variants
001: not fitted R9A R9B R9C R9D R9E R33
